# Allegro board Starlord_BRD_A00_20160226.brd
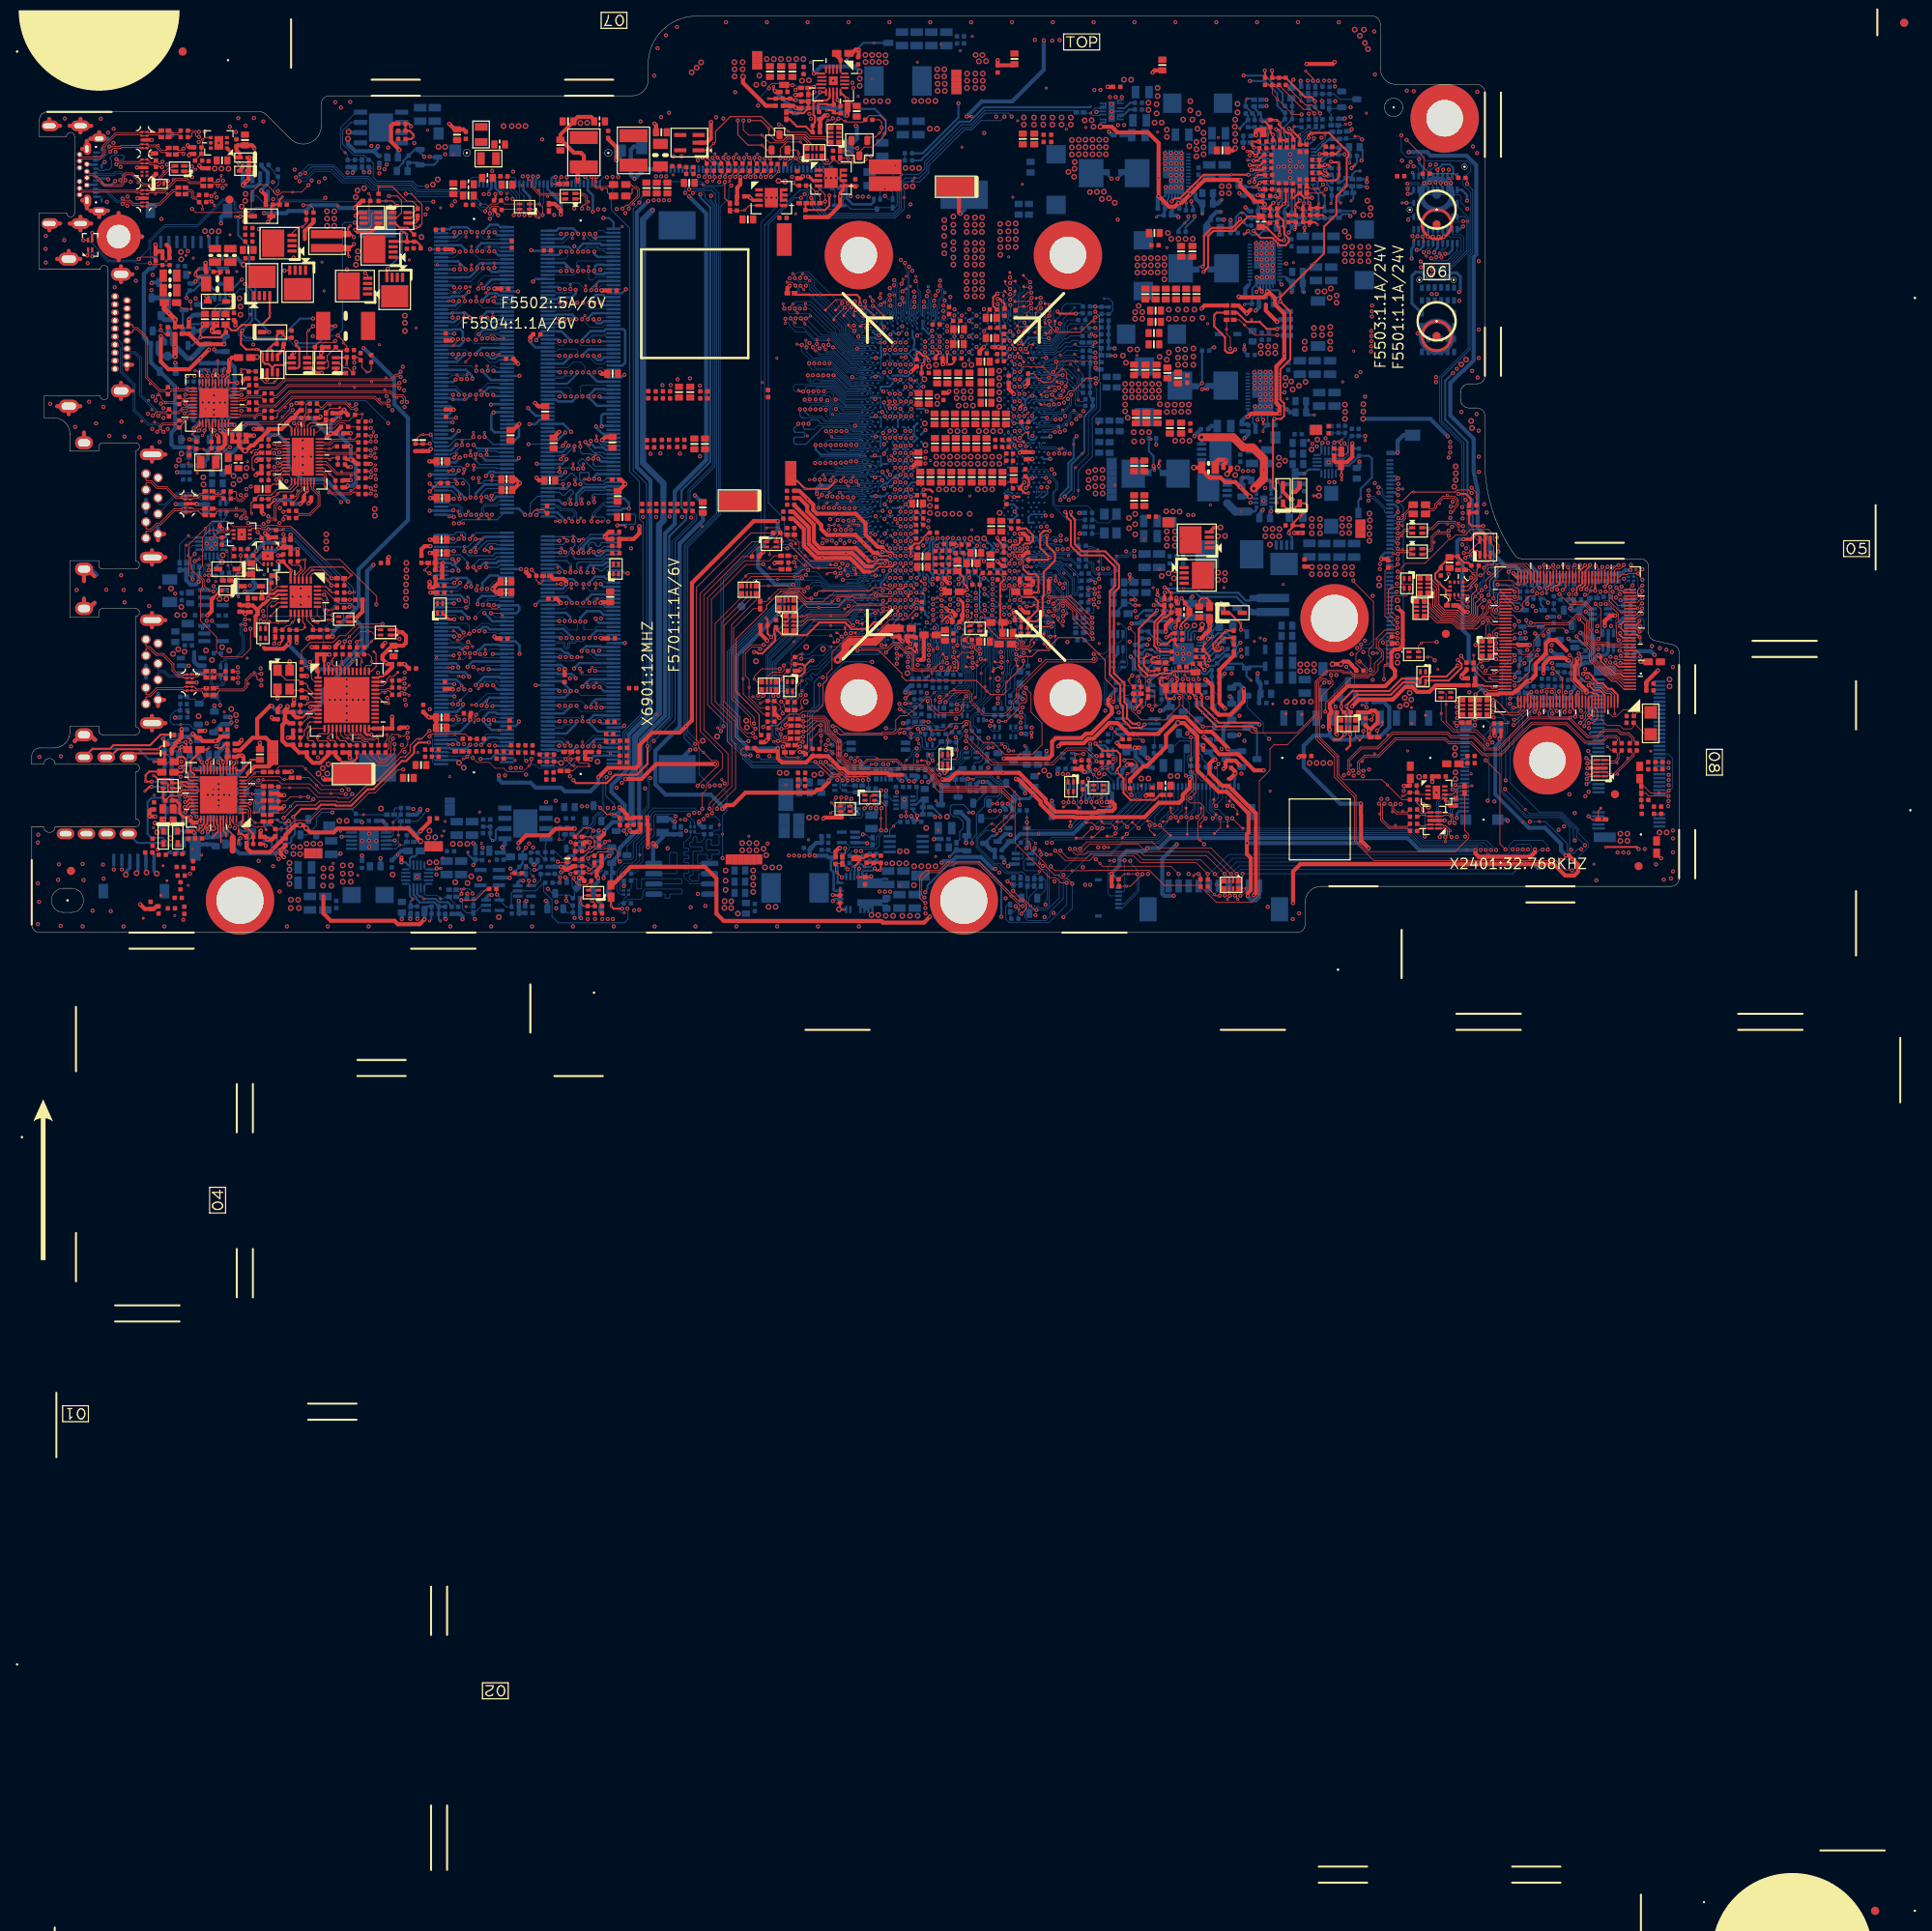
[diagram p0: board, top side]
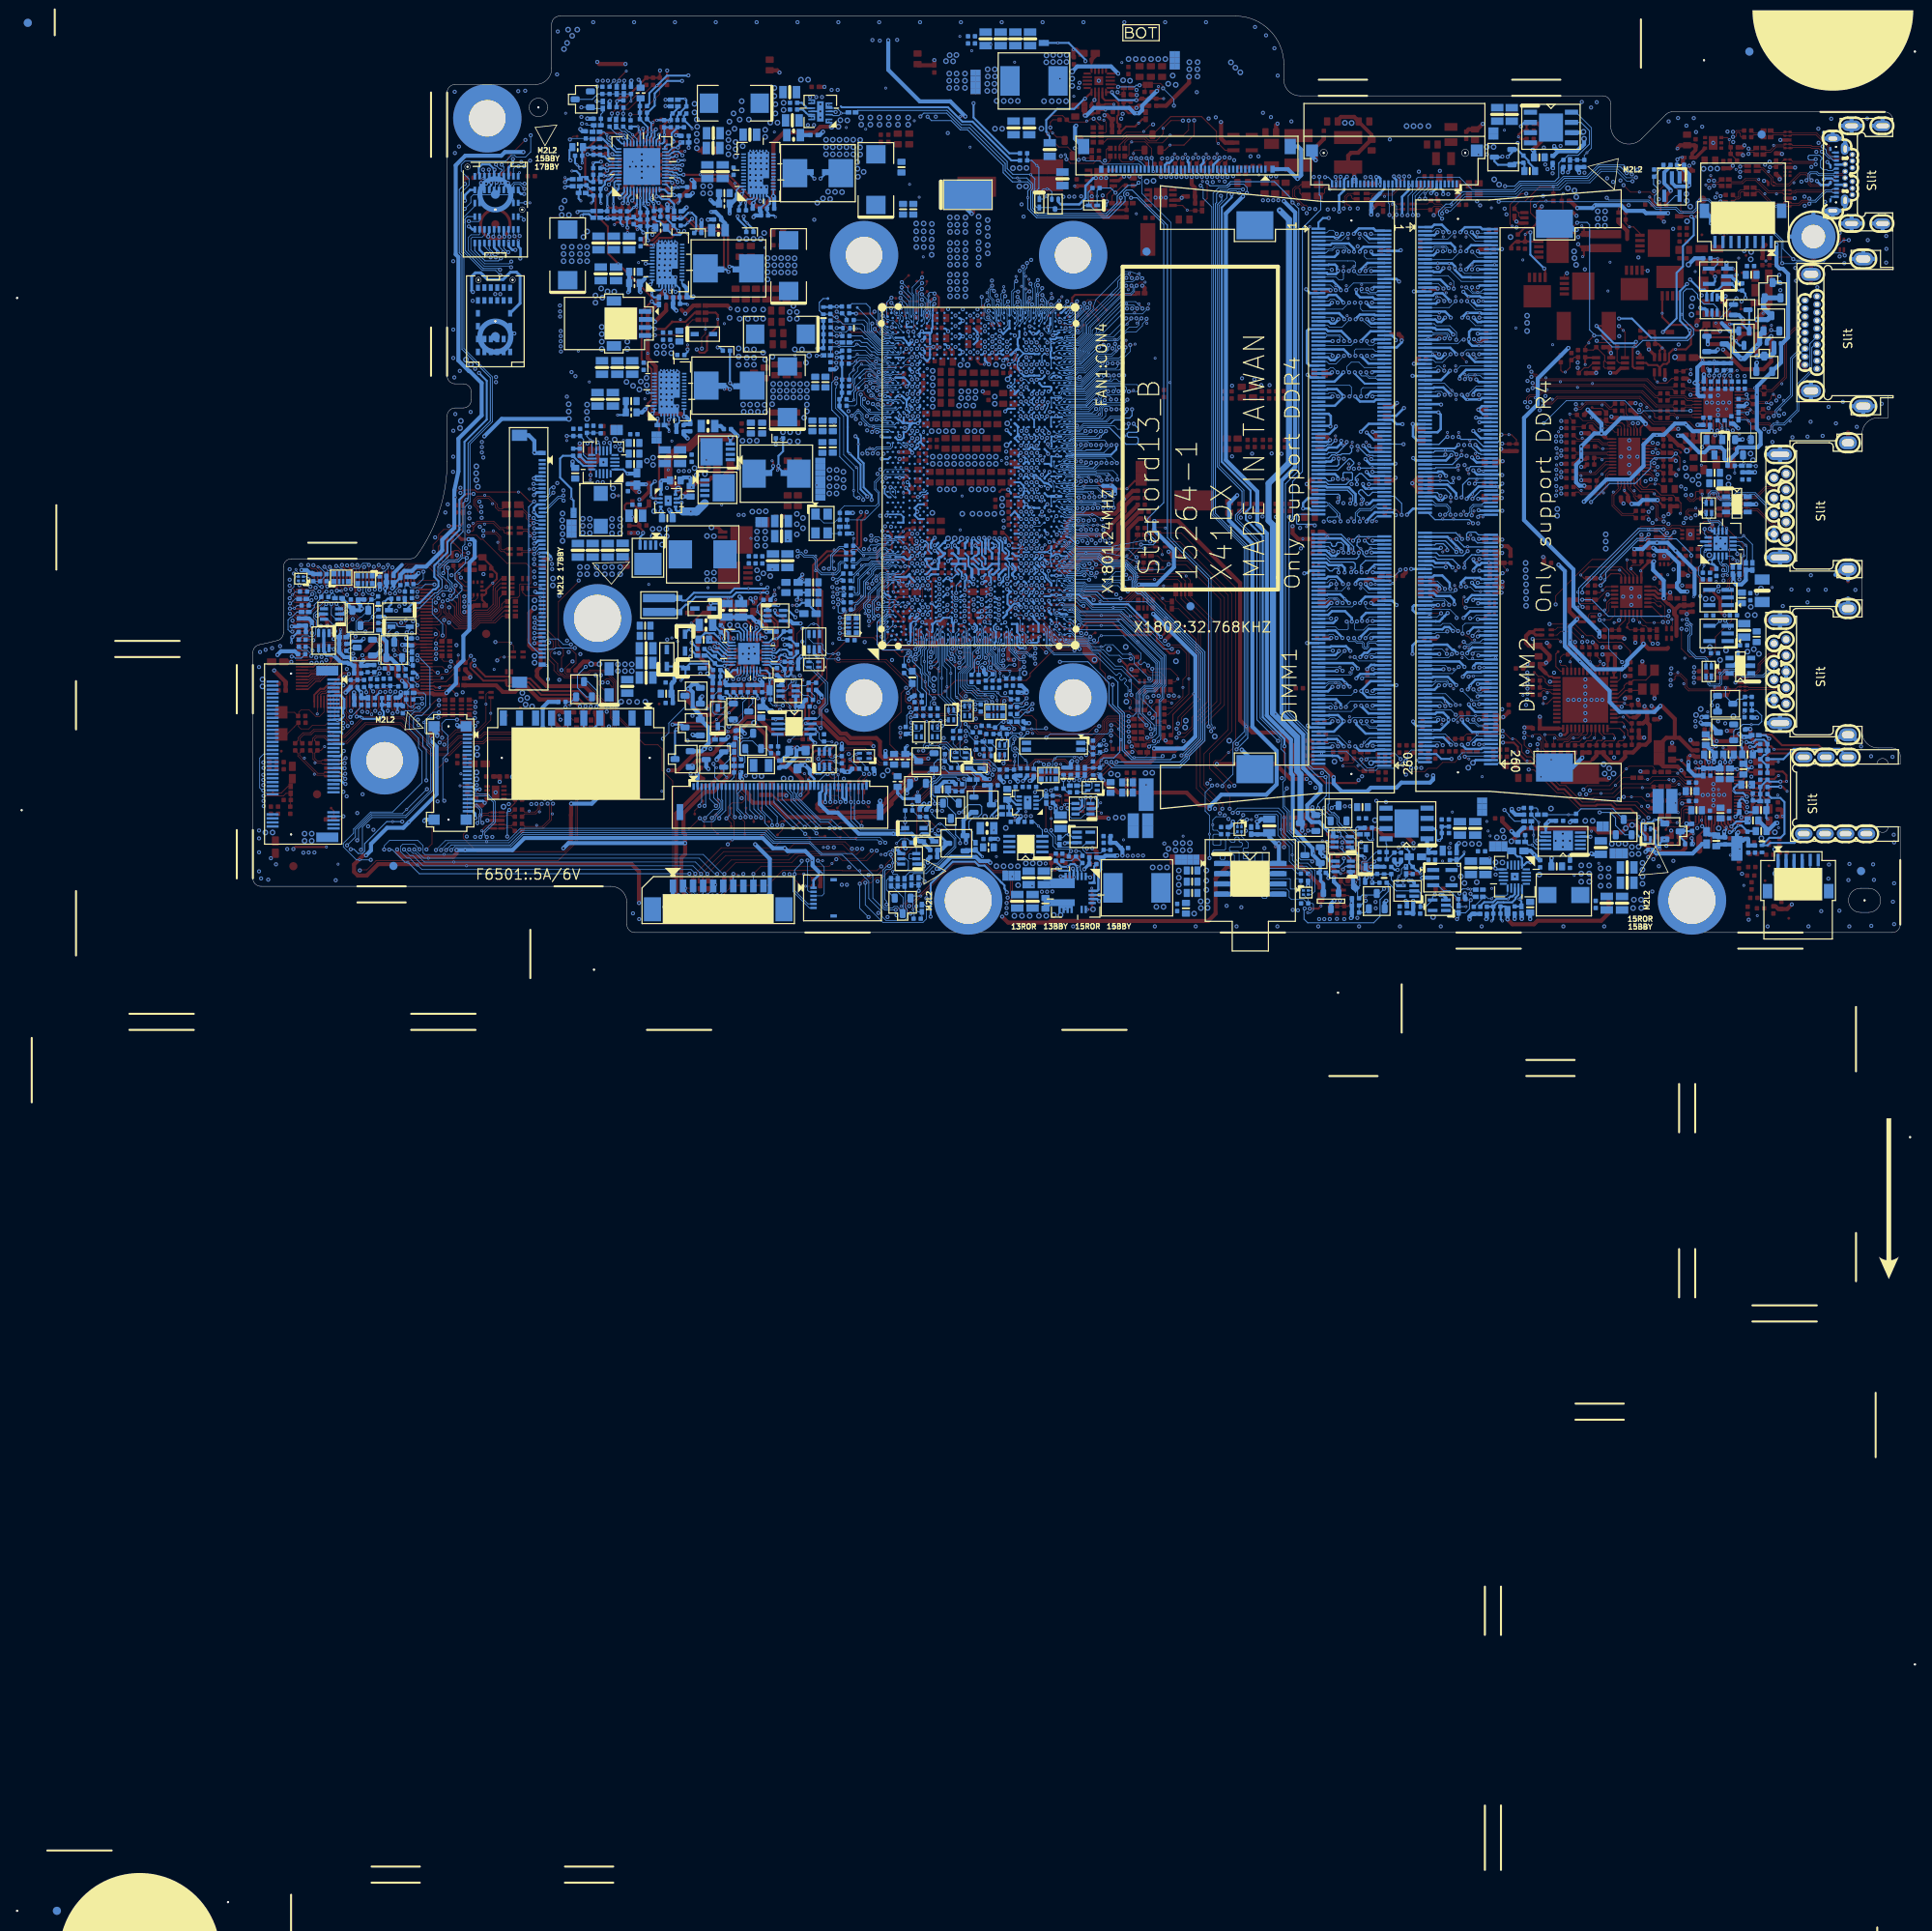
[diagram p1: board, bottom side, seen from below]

Outline 204.85 x 113.92 mm; copper layers: TOP, L2GND, L3, L4, L5VCC, L6, L7GND, BOTTOM. Coordinates in mm from the lower left corner of the outline.

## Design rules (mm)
constraint set DEFAULT: min track width 0.127, pair gap 0.102
net group DDR4_A_BA_40-MW: nets M_A_BA0 M_A_BA1
net group DDR4_A_BG_40-MW: nets M_A_BG0 M_A_BG1
net group DDR4_A_ODT10-MW: nets M_A_DIMA_ODT0 M_A_DIMA_ODT1
net group DDR4_B_BA_40-MW: nets M_B_BA0 M_B_BA1
net group DDR4_B_BG_40-MW: nets M_B_BG0 M_B_BG1
net group DDR4_B_ODT10-MW: nets M_B_DIMB_ODT0 M_B_DIMB_ODT1
net group DDR4_VREF_40: nets V_SM_VREF_CNTA V_SM_VREF_CNTB
net group FAN_TACH: nets FAN1_TACH FAN_TACH1_C
net group I2C_MUX_50: nets MUX_SW0_PD MUX_SW1_PD
net group I2C_TOUCH_PAD-MWS: nets I2C0_SCL_TCH_PAD I2C0_SDA_TCH_PAD
net group POWER_15M: nets Q6205_Q Q6502_D
net group SIGNAL_V_F_8_OHM-MW: nets CFG3 XDP_DBRESET#
net group SIGNAL_V_F_10MIL: nets BEEP FAN_TACH1
net group SIGNAL_V_F_16.5_SVID-MWS: nets VR_SVID_CLK VR_SVID_DATA
net group SIGNAL_V_F_50OHM: nets HDA_CODEC_SYNC HDA_SDIN0
net group XDP_TCLK-MWS: nets XDP_TCK_JTAGX XDP_TCLK
net group AUDIO_12MIL: nets CPVEE
net group AUDIO_BEEP_10MIL: nets AUD_HP1_JACK_L AUD_HP1_JACK_L1 AUD_HP1_JACK_R AUD_HP1_JACK_R1 AUD_PC_BEEP AUD_PC_BEEP_C AUD_PC_BEEP_R AUD_PORTA_L_R_B AUD_PORTA_R_R_B AUD_SENSE AUD_SENSE_A AUD_VREF CBN CBP HDA_SPKR_R JACK_PLUG JACK_PLUG_DET KBC_BEEP_R LINE1-L_C LINE1-L_R LINE1_L LINE1_R LINE1_VREFO_L LINE1_VREFO_R MIC2_VREFO_L MIC2_VREFO_R SPKR
net group AUDIO_BITCLK_50-MWS: nets CODEC_BITCLK_R HDA_BITCLK HDA_CODEC_BITCLK
net group AUDIO_DIGITAL_50-MWS: nets CODEC_SDOUT_R HDA_CODEC_SDIN0 HDA_CODEC_SDOUT HDA_RST# HDA_RST#_R HDA_SDOUT HDA_SYNC
net group CFG_50-MWS: nets CFG0 CFG1 CFG2 CFG4 CFG5 CFG6 CFG7 CFG8 CFG9 CFG10 CFG11 CFG12 CFG13 CFG14 CFG15 CFG16 CFG17 CFG18 CFG19
net group CLK_50-MWS: nets CLK_PCI_LPC CLK_PCI_LPC_MEC SUSCLK SUSCLK_R
net group COMP_20MIL: nets CPU_POPIRCOMP CSI2_COMP EMMC_RCOMP EOPIO_RCOMP PCH_POPIRCOMP SD_RCOMP SM_RCOMP_0 SM_RCOMP_1 SM_RCOMP_2 USBCOMP XCLK_BIASREF
net group CPU_50-MWS: nets CMP_VOUT1 H_PROCHOT#_R PQ4405_3 PWR_CHG_PROCHOT#
net group DDR4_A_CMD_40-MW: nets M_A_A0 M_A_A1 M_A_A2 M_A_A3 M_A_A4 M_A_A5 M_A_A6 M_A_A7 M_A_A8 M_A_A9 M_A_A10 M_A_A11 M_A_A12 M_A_A13 M_A_A14 M_A_A15 M_A_A16 M_A_ACT_N M_A_ALERT_N M_A_PARITY
net group DDR4_A_DATA_00_50-MW: nets M_A_DQ0 M_A_DQ1 M_A_DQ2 M_A_DQ3 M_A_DQ4 M_A_DQ5 M_A_DQ6 M_A_DQ7
net group DDR4_A_DATA_01_50-MW: nets M_A_DQ8 M_A_DQ9 M_A_DQ10 M_A_DQ11 M_A_DQ12 M_A_DQ13 M_A_DQ14 M_A_DQ15
net group DDR4_A_DATA_02_50-MW: nets M_A_DQ16 M_A_DQ17 M_A_DQ18 M_A_DQ19 M_A_DQ20 M_A_DQ21 M_A_DQ22 M_A_DQ23
net group DDR4_A_DATA_03_50-MW: nets M_A_DQ24 M_A_DQ25 M_A_DQ26 M_A_DQ27 M_A_DQ28 M_A_DQ29 M_A_DQ30 M_A_DQ31
net group DDR4_A_DATA_04_50--MW: nets M_A_DQ32 M_A_DQ33 M_A_DQ34 M_A_DQ35 M_A_DQ36 M_A_DQ37 M_A_DQ38 M_A_DQ39
net group DDR4_A_DATA_05_50-MW: nets M_A_DQ40 M_A_DQ41 M_A_DQ42 M_A_DQ43 M_A_DQ44 M_A_DQ45 M_A_DQ46 M_A_DQ47
net group DDR4_A_DATA_06_50-MW: nets M_A_DQ48 M_A_DQ49 M_A_DQ50 M_A_DQ51 M_A_DQ52 M_A_DQ53 M_A_DQ54 M_A_DQ55
net group DDR4_A_DATA_07_50-MW: nets M_A_DQ56 M_A_DQ57 M_A_DQ58 M_A_DQ59 M_A_DQ60 M_A_DQ61 M_A_DQ62 M_A_DQ63
net group DDR4_B_CMD_40--MW: nets M_B_A0 M_B_A1 M_B_A2 M_B_A3 M_B_A4 M_B_A5 M_B_A6 M_B_A7 M_B_A8 M_B_A9 M_B_A10 M_B_A11 M_B_A12 M_B_A13 M_B_A14 M_B_A15 M_B_A16 M_B_ACT_N M_B_ALERT_N M_B_PARITY
net group DDR4_B_DATA_00_50-MW: nets M_B_DQ0 M_B_DQ1 M_B_DQ2 M_B_DQ3 M_B_DQ4 M_B_DQ5 M_B_DQ6 M_B_DQ7
net group DDR4_B_DATA_01_50-MW: nets M_B_DQ8 M_B_DQ9 M_B_DQ10 M_B_DQ11 M_B_DQ12 M_B_DQ13 M_B_DQ14 M_B_DQ15
net group DDR4_B_DATA_02_50-MW: nets M_B_DQ16 M_B_DQ17 M_B_DQ18 M_B_DQ19 M_B_DQ20 M_B_DQ21 M_B_DQ22 M_B_DQ23
net group DDR4_B_DATA_03_50-MW: nets M_B_DQ24 M_B_DQ25 M_B_DQ26 M_B_DQ27 M_B_DQ28 M_B_DQ29 M_B_DQ30 M_B_DQ31
net group DDR4_B_DATA_04_50-MW: nets M_B_DQ32 M_B_DQ33 M_B_DQ34 M_B_DQ35 M_B_DQ36 M_B_DQ37 M_B_DQ38 M_B_DQ39
net group DDR4_B_DATA_05_50-MW: nets M_B_DQ40 M_B_DQ41 M_B_DQ42 M_B_DQ43 M_B_DQ44 M_B_DQ45 M_B_DQ46 M_B_DQ47
net group DDR4_B_DATA_06_50-MW: nets M_B_DQ48 M_B_DQ49 M_B_DQ50 M_B_DQ51 M_B_DQ52 M_B_DQ53 M_B_DQ54 M_B_DQ55
net group DDR4_B_DATA_07_50-MW: nets M_B_DQ56 M_B_DQ57 M_B_DQ58 M_B_DQ59 M_B_DQ60 M_B_DQ61 M_B_DQ62 M_B_DQ63
net group DDR4_CKE_40-MW: nets M_A_CKE0 M_A_CKE1 M_A_CS#0 M_A_CS#1 M_B_CKE0 M_B_CKE1 M_B_CS#0 M_B_CS#1
net group GND: nets MIC_GND
net group JTAG-MW: nets PCH_JTAG_TCK PCH_JTAG_TDI PCH_JTAG_TDO PCH_JTAG_TMS
net group KBC: nets KSI0 KSI1 KSI2 KSI3 KSI4 KSI5 KSI6 KSI7 KSO0 KSO1 KSO2 KSO3 KSO4 KSO5 KSO6 KSO7 KSO8 KSO9 KSO10 KSO11 KSO12 KSO13 KSO14 KSO15 KSO16
net group LCD_BKLT: nets BKLT_CTRL L_BKLT_CTRL LCD_BRIGHTNESS
net group LED: nets BAT1_LED# BAT2_LED# BATT_WHITE_LED# BATT_WHITE_LED_R# CAP_LED# CAP_LED_R# CHG_AMBER_LED# SATA_LED#
net group LED_20MIL: nets AMBER_LED_BAT BAT_AMBER BAT_WHITE CAP_LED CAP_LED_Q CHG_AMBER_LED_R# WHITE_LED_BAT
net group LPC-MWS: nets CLKRUN#_R LPC_FRAME#_DEBUG LPC_LAD0 LPC_LAD0_C LPC_LAD0_R LPC_LAD1 LPC_LAD1_C LPC_LAD1_R LPC_LAD2 LPC_LAD2_C LPC_LAD2_R LPC_LAD3 LPC_LAD3_C LPC_LAD3_R LPC_LFRAME# LPC_LFRAME#_R PCI_CLK_LPC0 PCI_CLK_LPC1 SERIRQ
net group OTHER_4MIL: nets +3VLP A5_TP A67_TP A70_TP AD_IA AUX_EN_WOWL BLON_OUT_C BLUETOOTH_EN BOARD_ID BOARD_ID1 BOARD_ID2 CFG CLKREQ_PCIE#1 CLKREQ_PCIE#2 CLKREQ_PCIE#3 CLKREQ_PCIE#4 CLKREQ_PCIE#5 CLKREQ_PEG#0 COMBO-GPI CPU_DP1_HPD CPU_DP_HPD_MUX CTL1 CTL2 CTL3 DBC_EN_R DBC_PANEL_EN DCIN_EN DDCBUF DGPU_PWR_EN DGPU_PWROK DGPU_PWROK_KBC DVSS EAPD# EC_MUTE# EC_WAKE# EDP_DISP_UTIL EDP_HPD EDP_HPD_CONN EQ FALL_INT2 FAN_PWM1_C FFS_INT2 FFS_INT2_Q FFS_INT2_Q_R GPD11/LANPHYPC GPP_B2/VRALERT# GPP_B4/CPU_GP3 GPP_B18/GSPI0_MOSI GPP_B22 GPP_B23/SML1ALERT# GPP_C2/SMBALERT# GPP_C5/SML0ALERT# GPP_E0/SATAXPCIE0/SATAGP0 GPP_E1/SATAXPCIE1/SATAGP1 GPP_E2/SATAXPCIE2/SATAGP2 GPP_E3/CPU_GP0 GSEN2_INT1_C_HUB GSEN2_INT1_ISH GSEN2_INT2 GSEN2_INT2_C_HUB GSEN2_INT2_ISH GSEN_INT1 GSEN_INT1_HUB GSEN_INT1_ISH GSEN_INT2 GSEN_INT2_HUB GSEN_INT2_ISH GYRO_DRDY_HUB GYRO_DRDY_ISH GYRO_INT GYRO_INT_C GYRO_INT_C_HUB GYRO_INT_ISH GYRO_INT_P11 H_CATERR# HDD_CT HDD_DEVSLP_R HDD_EN HDD_EN_PCH HDMI_EC_DET# HDMI_EC_DET#_C HOST_DEBUG_TX HPD_HDMI_CON HPD_HDMI_CON_C I_ADP I_SYS ICSP_CLR ILIM_HI ILIM_LO ILIM_SEL INT2_SELECT INT#_TYPEC_R INT_TP# IR_CAMERA_DET# IR_CAMERA_DET#_R ISET ISH_KB_DISABLE KB_CLOSE#_2 KB_DISABLE KB_DISABLE_HUB KB_LED_BL_DET_R KB_LED_DET_C KBC_PWRBTN# L_BKLT_EN L_BKLT_EN_EC LCD_TST_C ME_FWP_EC MODEL_ID MSATA_DEVSLP MSATA_DEVSLP_R MSM# MUX_EN MUX_EN_R MUX_HPD_PD MUX_I2C_EN OC_1 OC_2 OVER_CURRENT_P8# P_SYS PBAT_PRES1# PBAT_PRES# PCH_ALW_ON PCH_BATLOW# PCH_THERMTRIP# PCH_WAKE# PD4403_A PD4403_K PIRQA# PME# POWER_SW_IN# PQ4405_2 PQ4405_5 PQ4405_6 PQ4408_C PQ4408_E PRE PROC_SELECT# PS_ID_R PS_ID_R1 PSYS PWR_1D2V_EN PWR_2D5V_EN PWR_CHG_ACOK REXT SA0_CHA_DIM0 SA0_CHB_DIM0 SA1_CHA_DIM0 SA1_CHB_DIM0 SA2_CHA_DIM0 SA2_CHB_DIM0 SIO_EXT_SMI# SIO_EXT_WAKE# SIO_PWRBTN# SIO_SLP_A# SIO_SLP_S5# SIO_SLP_SUS# SKTOCC# SM_INTRUDER# SYS_PRES1# TOUCHPAD_INTR# USB2_ID USB2_VBUSSENSE USB_OC1# USB_OC2# USB_UART_SEL_D9 USBCHARGER_CB0 VBUS_PRODECT# VCREF0 VOL_DOWN# VOL_UP# VR_RDY VRAM_ID1 WIFI_RF_EN ZVM#
net group PECI-MW: nets PECI_EC
net group PLATFORM: nets 1D0V_S5_PWRGD 1D8S_EN_R# 1D8V_EN# 1D8V_EN_R# 1D8V_S5_PWROK 3V5V_S0_ON 3V_5V_POK# 3V_5V_POK_C +SDC_IN_SW +SDC_IN_SW_R1 ALL_SYS_PWRGD_R CPU_DP2_HPD CPU_DP_HPD_R DGPU_HOLD_RST# DS3_PWRCTL EDP_VDD_EN EN_EDRAM_VR GC6_FB_EN_MCP GPU_EVENT# GPU_EVENT_MCP# GSENSOR_CS GSENSOR_SDO H_CPUPWRGD H_VCCST_PWRGD HUB_PA1 HUB_PA2 HUB_PA3 HUB_PA4 HUB_PA5 HUB_PA6 IC_DELAY INT#_TYPEC KB_CLOSE#_2_R LVDS_VDD_EN_R MCU_BOOT0 MCU_OSCI MCU_OSCO MCU_RST# ME_SUS_PWR_ACK ME_SUS_PWR_ACK_R MUX_CDE MUX_CEQ MUX_CEXT MUX_DPEQ MUX_REXT MUX_SSDE MUX_SSEQ MUX_SW2_PD MUX_SW2_PD_R PCH_PLTRST# PCH_RSMRST# PD_CC1 PD_CC1_VCONN_CTRL PD_CC1_VCONN_CTRL_R PD_CC2 PD_CC2_VCONN_CTRL PD_CC2_VCONN_CTRL_R PD_RD1 PD_SWD_CLK PD_SWD_IO PD_VBUS_C_CTRL1 PD_VBUS_C_CTRL1_A PD_VBUS_DISCHG PD_VBUS_P_CTRL1 PD_VBUS_P_CTRL1_R PD_VBUS_R PD_VCCD PD_XRES PLT_RST#_DEBUG PM_RSMRST#_M PM_RSMRST#_R PTP_DIS# PWR_0D6V_S3EN PWR_0D6V_S5EN PWR_0D6V_VCNTL PWR_1D0V_EN PWR_1D0V_PG PWR_1D5V_EN PWR_1D8V_EN PWR_1D8V_POK PWR_2D5V_PG PWR_3D3V_EN PWR_3D3V_EN1 PWR_3V_PG PWR_5V_PG PWR_VCORE_EN RSMRST_PWRGD# RTCRST_ON SATA_ACT# SLP_LAN# SM_DRAMRST# SM_PGCNTL SM_PGCNTL_R SPK_DET# SRTC_RST# SSD_PEDET SUS_STAT#/LPCPD# SUSACK# SUSACK#_R SWCLK SWDIO TP_ON#_GATE TPS70933_EN TS#_DIMM0_1 TS#_DIMM1_1 U4006_CT U4301_IN USB_ADT_SW USB_ADT_SW_R USB_EN# USB_TYPEC_R USBDISABLE VBUS_PRODECT VCCSTG_EN_R VCCSTU_EN_R VCONN1 VCONN2
net group POWER_10M: nets 1.8V_RUN_FB 3D3V_GSEN2 3V5V_CT1 3V5V_CT2 5V_STB +3V_1D8V_AVDD +V1.00U_CPU +VCCAMPHYPLL_1P0 +VCCAPLL_1P0 +VCCCLK2 +VCCCLK4 +VCCCLK5 +VCCCOREG0 +VCCCOREG1 +VCCDSW_1P0 +VCCFUSEPRG +VCCPRTC_3P3 +VCCSFR +VCCST_CPU +VCCSTG BOOST_MON I_BATT LDO1_CAP LDO2_CAP LDO3_CAP MIC_CAP PWR_1D0V_BT PWR_1D0V_FB PWR_1D0V_FB_A PWR_1D0V_PFM PWR_1D0V_SS PWR_1D0V_TON PWR_1D2V_BYP PWR_1D2V_IMAX PWR_1D2V_VFB PWR_1D2V_VFB_R PWR_2D5V_FB PWR_3D3V_FB PWR_3D3V_VOUT PWR_5V_EN PWR_5V_EN1 PWR_5V_EN1_R PWR_5V_FB PWR_5V_FB_A PWR_5V_LDO PWR_5V_VOUT PWR_VCCGT_COMP PWR_VCCGT_COMP_R PWR_VCCGT_CSCOMP PWR_VCCGT_CSNA PWR_VCCGT_CSNB PWR_VCCGT_CSP1 PWR_VCCGT_CSP2 PWR_VCCGT_CSPA PWR_VCCGT_CSPB PWR_VCCGT_CSREF PWR_VCCGT_CSSUM PWR_VCCGT_DIFFOUT PWR_VCCGT_FB PWR_VCCGT_FB_R PWR_VCCGT_ICCMAX PWR_VCCGT_ILIM PWR_VCCGT_ILIM_R PWR_VCCGT_IOUT PWR_VCCGT_NTC PWR_VCCGT_PWMA PWR_VCCGT_PWMB PWR_VCCGT_TSENSE PWR_VCCGT_VCCA PWR_VCCGT_VCCB PWR_VCCGT_VSN PWR_VCCGT_VSN_R PWR_VCCGT_VSP PWR_VCCSA_COMP PWR_VCCSA_COMP_R PWR_VCCSA_CSN PWR_VCCSA_CSN_NTC PWR_VCCSA_CSP PWR_VCCSA_CSP1B PWR_VCCSA_ICCMAX PWR_VCCSA_ILIM PWR_VCCSA_IOUT PWR_VCCSA_VSN PWR_VCCSA_VSN_R PWR_VCCSA_VSP PWR_VCCSA_VSP_R PWR_VCCSA_VSP_RC PWR_VCORE_COMP PWR_VCORE_COMP_R PWR_VCORE_CSN PWR_VCORE_CSNNTC PWR_VCORE_CSP PWR_VCORE_CSP_1A PWR_VCORE_DRVON PWR_VCORE_ICCMAX PWR_VCORE_ILIM PWR_VCORE_IOUT PWR_VCORE_NTC PWR_VCORE_ROSC_COREGT PWR_VCORE_ROSC_SAUS PWR_VCORE_TSENSE PWR_VCORE_VCC_R PWR_VCORE_VR_RDY PWR_VCORE_VRHOT# PWR_VCORE_VRMP PWR_VCORE_VSN PWR_VCORE_VSN_R PWR_VCORE_VSP PWR_VCORE_VSP_R PWR_VCORE_VSP_RC Q6204_G TYPEC_5V TYPEC_5V_SW_R USB_TYPEC_DIS V0.85A_VID0 V0.85A_VID1 VCCRTCEXT
net group POWER_10M_POWER: nets AC_IN#_G ACLIM AD_OFF_L AD_OFF_R PQ3809_D PR_2 PWR_3D3V_FB2 PWR_ASGATE PWR_CHG_1 PWR_CHG_ACDET PWR_CHG_BATDRV PWR_CHG_BATPRES# PWR_CHG_BTST1 PWR_CHG_COMP PWR_CHG_FSET PWR_CHG_IADP PWR_CHG_IDCHG PWR_CHG_ILIM PWR_CHG_NTC PWR_CHG_PMON PWR_CHG_PROG PWR_CHG_REGN PWR_CHG_SRN_1 PWR_CHG_SRP_1 PWR_CMSRC PWR_OPCN PWR_OPCP PWR_VBAT PWR_VCCSA_PWM PWR_VCORE_ADDR_BOOT PWR_VCORE_PWM USB_ADT_D USB_ADT_D1 USB_ADT_R1 USB_TYPEC_SW VCCSA_SENSE VCCSENSE_EDRAM_VR VCCSENSE_EOPIO_VR VDD VSS_AY71 VSSSA_SENSE VSSSENSE_EDRAM_VR VSSSENSE_EOPIO_VR
net group POWER_20M: nets 1D8V_S0 3D3V_AUX_KBC_33 3D3V_AUX_S5 3D3V_SPIVCC1 5V_AUX_S5 +5V_AVDD +RTC_VCC +V_VREF_PATH1 +V_VREF_PATH2 EC_VTT ECVBAT PWR_1D2V_BOOT PWR_1D2V_BOOT_R PWR_3D3V_BOOT PWR_3D3V_BOOT_A PWR_5V_BOOT PWR_5V_BOOT_A PWR_VCCGT_SNUB_1 PWR_VCCGT_SNUB_2 TPAN_VDD VDDIO VREG3PD
net group POWER_20M_POWER: nets 3D3V_MCU BKLGT_PWM CPVDD KB_BL_CTRL# PWR_CHG_VCC PWR_VCCGT_BOOTA PWR_VCCGT_BOOTA_RC PWR_VCCGT_BOOTB PWR_VCCGT_BOOTB_RC PWR_VCCSA_BST PWR_VCCSA_BST_RC PWR_VCCSA_SNUB PWR_VCORE_BOOT PWR_VCORE_BOOT_RC PWR_VCORE_SNUB PWR_VCORE_VCC
net group POWER_25M: nets PQ3802_1 PS_ID_R2 PSID_DISABLE#_R_C
net group POWER_40M: nets DDR_VREF_S3
net group POWER_40M_POWER: nets PWR_VCCSA_DRVH
net group PWR_DISB: nets PWR_VCCGT_DISB#_A PWR_VCCGT_DISB#_B PWR_VCORE_DISB#
net group REF10M: nets VR_CAP
net group SIGNAL_V_F_4MIL: nets 3V_5V_POK AC_DIS AC_PRESENT CLKRUN# FAN1_PWM GPD2/LAN_WAKE# GSEN2_INT1 GSEN2_INT1_C GSEN2_INT2_C GYRO_DRDY HDD_DEVSLP HDD_FALL_INT ITP_PMODE KB_DET# LCD_TST LCD_TST_EN LID_CL_SIO# PLT_RST# RESET_OUT# RTC_DET# USB_CHG_EN USB_OC0# USB_OC3# VCCSTU_EN VR_EN
net group SIGNAL_V_F_5MIL: nets 1D2V_VTT_PWRGD 1D8S_EN# 3V_5V_EN ACOK# ALL_SYS_PWRGD ALWON DDR4_DRAMRST# EXT_PWR_GATE# GC6_FB_EN PANEL_BKEN_EC PCH_DPWROK PM_PCH_PWROK PM_RSMRST# RTC_RST# SIO_SLP_S0# SIO_SLP_S3# SIO_SLP_S4# SYS_PWROK TOUCH_PANEL_INTR# TP_EN#
net group SIGNAL_V_F_10MIL-2: nets ACOK_IN ACOK_IN_M DC_IN_OK HW_ACAVIN_NB#
net group SIGNAL_V_F_14_OHM-MW: nets VR_SVID_ALERT#
net group SIGNAL_V_F_15_OHM-MW: nets H_PECI
net group SIGNAL_V_F_16.5_OHM-MWS: nets PCH_SMBCLK PCH_SMBDATA SPI_CLK_ROM SPI_CS_ROM_N0 SPI_HOLD_ROM SPI_SI_ROM SPI_WP_ROM
net group SIGNAL_V_F_25MIL: nets PS_ID
net group SIGNAL_V_F_50_OHM-MWS: nets CCG2_I2C_SCL CCG2_I2C_SDA H_PROCHOT# MEM_SMBCLK MEM_SMBDATA
net group SMBUS_10MIL: nets PBAT_SMBCLK1 PBAT_SMBDAT1 SMBCLK1 SMBDA1
net group SMBUS_50-MWS: nets CLK_TP_SIO CPU_DP1_CTRL_CLK CPU_DP1_CTRL_DATA CPU_DP2_CTRL_CLK CPU_DP2_CTRL_DATA DAT_TP_SIO DDC_CLK_HDMI DDC_CLK_PH1 DDC_DATA_HDMI DDC_DATA_PH2 DMIC_CLK DMIC_CLK_C DMIC_CLK_R DMIC_DATA DMIC_DATA_C DMIC_DATA_R I2C0_SCL I2C0_SCL_R I2C0_SDA I2C0_SDA_R I2C1_SCL I2C1_SDA I2C_CLK_PD I2C_DATA_PD ICSP_CLOCK ICSP_DATA PWR_CHG_SCL PWR_CHG_SDA SENSOR_I2C_SCL SENSOR_I2C_SCL_2G SENSOR_I2C_SCL_HUB SENSOR_I2C_SDA SENSOR_I2C_SDA_2G SENSOR_I2C_SDA_HUB SMBCLK2 SMBCLK3 SMBDA2 SMBDA3 SML0_SMBCLK SML0_SMBDATA SML1_SMBCLK SML1_SMBDATA THM_SML1_CLK THM_SML1_DATA TPCLK_C TPDATA_C
net group SPI_50-MWS: nets EC_SPI_CLK EC_SPI_MISO EC_SPI_MOSI SIO_EXT_SCI# SIO_RCIN# SPI_CLK_CPU SPI_CLK_ROM_R SPI_CS_CPU_N0 SPI_HOLD_CPU SPI_HOLD_ROM_R SPI_SI_CPU SPI_SI_ROM_R SPI_SO_CPU SPI_SO_ROM SPI_SO_ROM_R SPI_WP_CPU SPI_WP_ROM_R
net group SVID-MW: nets H_CPU_SVIDALRT# H_CPU_SVIDCLK H_CPU_SVIDDAT PWR_VCORE_ALERT# PWR_VCORE_SCLK PWR_VCORE_SDIO
net group T8-MW: nets CMP_VIN0 CMP_VIN0_R CMP_VOUT0 VD_IN1_C
net group TESTPD_4MIL: nets AV1_TP AV71_TP B71_TP BA1_TP BA2_TP BA71_TP BB67_TP BB70_TP C1_TP CPU_A16_TP CPU_D1_TP CPU_D4_TP CPU_D5_TP CPU_D6_TP E71_TP RSVD_F65 RSVD_G65 RSVD_TP_AK12 RSVD_TP_AK13 RSVD_TP_AW70 RSVD_TP_AW71 RSVD_TP_BA68 RSVD_TP_BA70 RSVD_TP_BB68 RSVD_TP_BB69 TP1_AY4 TP2_BB3 TP4_BB5 TP5_AU5 TP6_AT5
net group THERM_SHUTDOWN: nets ALERT# PURE_HW_SHUTDOWN# T_CRIT# THERM_SYS_SHDN#
net group TYPEC_10MIL: nets 3D3V_MUX
net group UART_MW-MW: nets LPSS_UART2_RXD LPSS_UART2_TXD UART0_CTS# UART0_RTS# UART0_TXD UART1_CTS# UART1_RTS#
net group XDP-MW: nets XDP_PRDY# XDP_PREQ# XDP_TDI XDP_TDO_CPU XDP_TMS XDP_TRST#
net group XDP_BPM-MW: nets XDP_BPM0 XDP_BPM1 XDP_BPM2 XDP_BPM3
net group XTAL-MW: nets RTC_X1 RTC_X2 XTAL1 XTAL2 XTAL24_IN XTAL24_OUT XTAL24_OUT_R

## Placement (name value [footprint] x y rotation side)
AFTP2601  AFTE14P-GP  [AFTE14P-75]  152.7 75.91 0 top
AFTP2602  AFTE14P-GP  [AFTE14P-75]  150.8 75.53 0 top
AFTP2603  AFTE14P-GP  [AFTE14P-75]  151.56 77.44 0 top
AFTP2604  AFTE14P-GP  [AFTE14P-75]  153.47 78.07 0 top
AFTP2901  AFTE14P-GP  [AFTE14P-75]  16.81 6.44 90 top
AFTP2902  AFTE14P-GP  [AFTE14P-75]  16.33 8.3 90 top
AFTP2903  AFTE14P-GP  [AFTE14P-75]  16.05 4.61 0 top
AFTP2904  AFTE14P-GP  [AFTE14P-75]  13.87 1.77 0 top
AFTP4301  DO NOT STUFF  [AFTE14P-75]  19.66 82.01 0 top
AFTP4302  DO NOT STUFF  [AFTE14P-75]  19.18 84.17 0 top
AFTP4303  DO NOT STUFF  [AFTE14P-75]  24.66 86.73 0 top
AFTP4304  DO NOT STUFF  [AFTE14P-75]  19.84 77.49 0 top
AFTP4305  DO NOT STUFF  [AFTE14P-75]  21.92 86.58 0 top
AFTP4306  DO NOT STUFF  [AFTE14P-75]  173.3 26.99 0 top
AFTP4307  DO NOT STUFF  [AFTE14P-75]  171.58 27.96 0 top
AFTP4308  DO NOT STUFF  [AFTE14P-75]  171.58 26 0 top
AFTP4309  DO NOT STUFF  [AFTE14P-75]  165.12 23.89 0 top
AFTP4310  DO NOT STUFF  [AFTE14P-75]  163.5 22.8 0 top
AFTP4311  DO NOT STUFF  [AFTE14P-75]  161.92 23.99 0 top
AFTP4312  DO NOT STUFF  [AFTE14P-75]  154.33 28.41 0 top
AFTP4313  DO NOT STUFF  [AFTE14P-75]  157.96 27.12 0 top
AFTP4314  DO NOT STUFF  [AFTE14P-75]  155.95 27.17 0 top
AFTP4315  DO NOT STUFF  [AFTE14P-75]  167.94 26.15 0 top
AFTP4601  DO NOT STUFF  [AFTE14P-75]  164.54 98.98 90 top
AFTP6301  AFTE14P-GP  [AFTE14P-75]  202.36 17.34 0 top
AFTP6303  AFTE14P-GP  [AFTE14P-75]  195.12 15.46 0 top
AFTP6304  AFTE14P-GP  [AFTE14P-75]  201.32 22.55 0 top
AFTP6501  AFTE14P-GP  [AFTE14P-75]  134.95 13.78 0 top
AFTP6502  AFTE14P-GP  [AFTE14P-75]  129.87 11.75 0 top
AFTP6503  AFTE14P-GP  [AFTE14P-75]  131.14 13.66 0 top
AFTP6504  AFTE14P-GP  [AFTE14P-75]  146.99 16.55 0 top
AFTP6505  AFTE14P-GP  [AFTE14P-75]  131.8 11.85 0 top
AFTP6506  AFTE14P-GP  [AFTE14P-75]  133.7 11.98 0 top
AFTP6507  AFTE14P-GP  [AFTE14P-75]  145.41 15.46 0 top
AFTP6508  AFTE14P-GP  [AFTE14P-75]  133.04 13.78 0 top
AFTP6509  AFTE14P-GP  [AFTE14P-75]  135.61 11.78 0 top
AFTP6510  AFTE14P-GP  [AFTE14P-75]  138.76 13.86 0 top
AFTP6511  AFTE14P-GP  [AFTE14P-75]  143.53 15.49 0 top
AFTP6512  AFTE14P-GP  [AFTE14P-75]  136.85 13.68 0 top
AFTP6513  AFTE14P-GP  [AFTE14P-75]  143.69 12.21 0 top
AFTP6514  AFTE14P-GP  [AFTE14P-75]  141.6 12.11 0 top
AFTP6515  AFTE14P-GP  [AFTE14P-75]  139.62 12.13 0 top
AFTP6516  AFTE14P-GP  [AFTE14P-75]  141.63 15.49 0 top
AFTP6517  AFTE14P-GP  [AFTE14P-75]  140.66 13.78 0 top
AFTP6518  AFTE14P-GP  [AFTE14P-75]  142.57 13.78 0 top
AFTP6519  AFTE14P-GP  [AFTE14P-75]  145.36 13.17 0 top
AFTP6520  AFTE14P-GP  [AFTE14P-75]  147.06 12.28 0 top
AFTP6521  AFTE14P-GP  [AFTE14P-75]  148.72 13.2 0 top
AFTP6522  AFTE14P-GP  [AFTE14P-75]  148.92 16.35 0 top
AFTP6523  AFTE14P-GP  [AFTE14P-75]  149.91 14.72 0 top
AFTP6524  AFTE14P-GP  [AFTE14P-75]  150.62 12.95 0 top
AFTP6529  AFTE14P-GP  [AFTE14P-75]  137.97 18.25 0 top
AFTP6530  AFTE14P-GP  [AFTE14P-75]  136.83 20.92 0 top
AFTP6531  AFTE14P-GP  [AFTE14P-75]  125.25 19.75 0 top
AFTP6532  AFTE14P-GP  [AFTE14P-75]  128.29 15.61 0 top
AFTP6533  AFTE14P-GP  [AFTE14P-75]  130.22 15.51 0 top
AFTP6534  AFTE14P-GP  [AFTE14P-75]  132.18 15.49 0 top
AFTP6535  AFTE14P-GP  [AFTE14P-75]  134.11 15.66 0 top
AFTP6536  AFTE14P-GP  [AFTE14P-75]  123.8 12.95 0 top
AFTP6537  AFTE14P-GP  [AFTE14P-75]  129.16 13.81 0 top
AFTP6538  AFTE14P-GP  [AFTE14P-75]  148.84 19.12 0 top
AFTP6539  AFTE14P-GP  [AFTE14P-75]  147.27 14.67 0 top
BATT1  ETY-CON10-28-GP  [50299-01001-002]  164.7 21.71 180 bottom
C701  SC10U6D3V3MX-GP  [C603H38]  115.21 68.93 0 top
C702  SC10U6D3V3MX-GP  [C603H38]  116.61 68.93 0 top
C703  SC10U6D3V3MX-GP  [C603H38]  113.87 68.93 0 top
C704  SC10U6D3V3MX-GP  [C603H38]  112.6 68.93 0 top
C715  SC10U6D3V3MX-GP  [C603H38]  110.26 59.02 0 top
C716  SC1U10V2KX-1GP  [C402H22]  123.92 46.78 180 top
C717  SC1U10V2KX-1GP  [C402H22]  123.92 39.34 180 top
C718  SCD1U16V2KX-3GP  [C402H22]  77.4 60.76 0 top
C719  SC1U10V2KX-1GP  [C402H22]  76.51 60.76 0 top
C720  SCD1U16V2KX-3GP  [C402H22]  120.88 48.48 180 top
C721  SCD1U16V2KX-3GP  [C402H22]  120.88 46.8 0 top
C1101  SC1U10V2KX-1GP  [C402H22]  121.49 60.8 180 top
C1102  DO NOT STUFF  [C402H22]  126.77 98.72 180 top
C1103  DO NOT STUFF  [C402H22]  112.47 75.58 90 top
C1104  DO NOT STUFF  [C402H22]  118.31 72 270 top
C1105  SC1U10V2KX-1GP  [C402H22]  125.83 98.72 180 top
C1106  DO NOT STUFF  [C402H22]  139.67 85.44 90 top
C1107  SC1U10V2KX-1GP  [C402H22]  119.63 75.18 90 top
C1108  DO NOT STUFF  [C402H22]  110.41 51.48 270 top
C1109  SC1U10V2KX-1GP  [C402H22]  112.52 53.36 180 top
C1110  SC1U10V2KX-1GP  [C402H22]  110.54 54.37 270 top
C1111  SC1U10V2KX-1GP  [C402H22]  110.44 52.29 270 top
C1112  SC22U6D3V3MX-1-GP  [C603H40]  118.49 36.16 270 top
C1113  SC22U6D3V3MX-1-GP  [C603H40]  110.77 45.46 270 top
C1114  SC1U10V2KX-1GP  [C402H22]  120.11 44.31 180 top
C1115  SC22U6D3V3MX-1-GP  [C603H40]  119.23 46.35 180 top
C1116  SC1U10V2KX-1GP  [C402H22]  113.64 46.6 90 top
C1117  SC1U10V2KX-1GP  [C402H22]  113.69 47.46 90 top
C1118  SC22U6D3V3MX-1-GP  [C603H40]  117.4 47.18 90 top
C1119  SC1U10V2KX-1GP  [C402H22]  115.37 47.18 270 top
C1120  SC10U6D3V3MX-GP  [C603H38]  116.94 45.91 270 top
C1121  SC1U10V2KX-1GP  [C402H22]  116.08 48.23 270 top
C1122  SC22U6D3V3MX-1-GP  [C603H40]  113.56 36.95 0 top
C1123  SC10U6D3V3MX-GP  [C603H38]  110.77 46.75 270 top
C1124  SC1U10V2KX-1GP  [C402H22]  120.67 60.8 180 top
C1125  SC1U10V2KX-1GP  [C402H22]  119.81 60.8 180 top
C1126  SC1U10V2KX-1GP  [C402H22]  121.18 59.1 180 top
C1127  SC1U10V2KX-1GP  [C402H22]  122.02 59.1 180 top
C1202  SC10U6D3V3MX-GP  [C603H38]  63.85 64.76 180 top
C1203  SC10U6D3V3MX-GP  [C603H38]  64.9 60.85 180 top
C1204  SC10U6D3V3MX-GP  [C603H38]  64.43 56.2 270 top
C1205  SC10U6D3V3MX-GP  [C603H38]  72.86 54.24 180 top
C1206  SC10U6D3V3MX-GP  [C603H38]  72.21 60.93 180 top
C1207  SC1U10V2KX-1GP  [C402H22]  73.56 21.15 90 top
C1208  SC10U6D3V3MX-GP  [C603H38]  73.46 51.65 90 top
C1209  SC10U6D3V3MX-GP  [C603H38]  71.93 41.72 0 top
C1210  SC10U6D3V3MX-GP  [C603H38]  72.24 69.46 270 top
C1211  SC4D7U6D3V2MX-1-GP  [C402H22]  71.42 24.22 180 top
C1212  SC4D7U6D3V2MX-1-GP  [C402H22]  72.31 24.22 180 top
C1213  SC1U10V2KX-L1-GP  [C402H22]  73.56 21.99 90 top
C1214  SC1U10V2KX-1GP  [C402H22]  72.29 79.8 270 top
C1215  SC1U10V2KX-1GP  [C402H22]  62.81 74.36 270 top
C1216  SC1U10V2KX-1GP  [C402H22]  64.11 84.78 90 top
C1217  SC1U10V2KX-1GP  [C402H22]  64.69 41.49 90 top
C1218  SC1U10V2KX-1GP  [C402H22]  66.27 31.59 180 top
C1219  SC1U10V2KX-1GP  [C402H22]  72.63 56.31 90 top
C1220  SC1U10V2KX-1GP  [C402H22]  72.08 36.57 270 top
C1221  SC1U10V2KX-1GP  [C402H22]  72.03 26.18 270 top
C1222  SCD022U16V2KX-3GP  [C402H22]  72.61 48.92 270 top
C1223  SC4D7U6D3V2MX-1-GP  [C402H22]  64.95 21.68 180 top
C1224  SC4D7U6D3V2MX-1-GP  [C402H22]  63.17 21.68 180 top
C1225  SC1U10V2KX-1GP  [C402H22]  64.44 19.9 90 top
C1226  SC1U10V2KX-1GP  [C402H22]  64.44 19.02 90 top
C1227  SC4D7U6D3V2MX-1-GP  [C402H22]  64.06 21.68 180 top
C1228  SCD1U16V2KX-L-GP  [C402H22]  70.08 22.44 90 top
C1229  SCD1U16V2KX-3GP  [C402H22]  72.63 47.18 90 top
C1230  SC4D7U6D3V2MX-1-GP  [C402H22]  50.6 22.32 180 top
C1231  SC4D7U6D3V2MX-1-GP  [C402H22]  62.28 22.83 180 top
C1232  SC4D7U6D3V2MX-1-GP  [C402H22]  73.58 22.95 90 top
C1301  SCD1U16V2KX-3GP  [C402H22]  50.85 42.26 270 top
C1303  SC10U6D3V3MX-GP  [C603H38]  59.54 61.81 180 top
C1304  SC10U6D3V3MX-GP  [C603H38]  58.98 42.31 270 top
C1305  SC10U6D3V3MX-GP  [C603H38]  58.98 43.65 270 top
C1306  SC10U6D3V3MX-GP  [C603H38]  59.08 55.01 90 top
C1307  SC10U6D3V3MX-GP  [C603H38]  59.05 56.35 90 top
C1308  SC10U6D3V3MX-GP  [C603H38]  50.95 47.18 270 top
C1309  SC10U6D3V3MX-GP  [C603H38]  51.03 54.02 270 top
C1310  SC10U6D3V3MX-GP  [C603H38]  51 58.56 270 top
C1311  SC4D7U6D3V2MX-1-GP  [C402H22]  61.39 22.83 180 top
C1312  SC4D7U6D3V2MX-1-GP  [C402H22]  60.5 22.83 180 top
C1313  SC1U10V2KX-1GP  [C402H22]  58.7 22.06 180 top
C1314  SC1U10V2KX-L1-GP  [C402H22]  57.81 22.06 180 top
C1315  SC1U10V2KX-1GP  [C402H22]  51.51 64.56 180 top
C1316  SC1U10V2KX-1GP  [C402H22]  51.38 30.73 0 top
C1317  SC1U10V2KX-1GP  [C402H22]  54.18 27.27 90 top
C1318  SC1U10V2KX-1GP  [C402H22]  58.72 36.54 270 top
C1319  SC1U10V2KX-1GP  [C402H22]  51.48 74.03 0 top
C1320  SC1U10V2KX-1GP  [C402H22]  59.43 71.31 90 top
C1321  SC1U10V2KX-1GP  [C402H22]  58.8 80.03 270 top
C1322  SC1U10V2KX-1GP  [C402H22]  50.98 84.93 90 top
C1323  SCD022U16V2KX-3GP  [C402H22]  50.6 44.16 90 top
C1324  SC10U6D3V3MX-GP  [C603H38]  48.41 20.82 270 top
C1325  SC10U6D3V3MX-GP  [C603H38]  46.84 19.22 270 top
C1326  SC1U10V2KX-1GP  [C402H22]  49.76 22.29 180 top
C1327  SC1U10V2KX-1GP  [C402H22]  48.92 22.29 180 top
C1328  SCD1U16V2KX-L-GP  [C402H22]  56.54 22.52 90 top
C1329  SC2D2U10V3KX-L-GP  [C603H36]  50.93 25.44 270 top
C1330  SC4D7U6D3V2MX-1-GP  [C402H22]  59.61 22.83 180 top
C1331  SC4D7U6D3V2MX-1-GP  [C402H22]  73.58 23.84 90 top
C1601  SCD1U16V2KX-3GP  [C402H22]  130.66 46.37 90 bottom
C1602  SCD1U16V2KX-3GP  [C402H22]  130.66 45.48 90 bottom
C1605  SCD22U10V2KX-1GP  [C402H22]  130.94 42.82 90 bottom
C1606  SCD22U10V2KX-1GP  [C402H22]  130.94 41.93 90 bottom
C1607  SCD22U10V2KX-1GP  [C402H22]  130.94 40.15 90 bottom
C1608  SCD22U10V2KX-1GP  [C402H22]  130.94 41.04 90 bottom
C1609  SCD22U10V2KX-1GP  [C402H22]  130.99 43.73 90 bottom
C1610  SCD22U10V2KX-1GP  [C402H22]  130.99 44.62 90 bottom
C1611  SCD22U10V2KX-1GP  [C402H22]  130.63 47.19 90 bottom
C1612  SCD22U10V2KX-1GP  [C402H22]  130.63 48.08 90 bottom
C1701  SC220P50V2KX-3GP  [C402H22]  113.56 22.8 270 bottom
C1702  SCD1U16V2KX-3GP  [C402H22]  61.8 3.24 90 bottom
C1703  SCD1U16V2KX-3GP  [C402H22]  61.82 2.43 90 bottom
C1704  SC10U6D3V3MX-GP  [C603H38]  98.19 18.03 0 bottom
C1710  SCD47U10V2KX-GP  [C402H22]  67.56 8.7 0 top
C1711  SCD01U50V2KX-1GP  [C402H22]  65.05 7.74 0 bottom
C1801  SC15P50V2JN-2-GP  [C402H22]  131.42 52.16 270 bottom
C1802  SC15P50V2JN-2-GP  [C402H22]  131.42 49.6 270 bottom
C1803  SC3P50V2CN-1-GP  [C402H22]  100.38 21.71 0 bottom
C1804  SC3P50V2CN-1-GP  [C402H22]  100.38 23.41 180 bottom
C1805  SC1U10V2KX-1GP  [C402H22]  70.03 2.84 0 top
C1806  SC1U10V2KX-1GP  [C402H22]  67.74 4.26 270 bottom
C2101  SC1U10V2KX-1GP  [C402H22]  120.93 45.13 0 top
C2102  SC1U10V2KX-1GP  [C402H22]  95.73 19.85 90 top
C2103  SC1U10V2KX-1GP  [C402H22]  109.93 36.21 180 top
C2104  SC1U10V2KX-1GP  [C402H22]  109.98 49.42 180 top
C2105  SC1U10V2KX-1GP  [C402H22]  112.39 45.3 180 top
C2106  SC1U10V2KX-1GP  [C402H22]  112.39 46.98 0 top
C2107  SC1U10V2KX-1GP  [C402H22]  113.09 44.01 90 top
C2108  SC1U10V2KX-1GP  [C402H22]  114.6 36.75 0 top
C2109  SC1U10V2KX-1GP  [C402H22]  116.89 44.87 270 top
C2110  SCD1U16V2KX-3GP  [C402H22]  114.07 45.3 180 top
C2111  SCD1U16V2KX-3GP  [C402H22]  113.23 45.3 180 top
C2112  SCD1U16V2KX-3GP  [C402H22]  91.06 38.19 270 top
C2113  SC22U6D3V3MX-1-GP  [C603H40]  121.36 37.25 90 top
C2114  SC22U6D3V3MX-1-GP  [C603H40]  115.11 45.58 180 top
C2115  SC22U6D3V3MX-1-GP  [C603H40]  135.18 42.26 90 bottom
C2116  SC1U10V2KX-1GP  [C402H22]  110.41 50.66 270 top
C2117  SC1U10V2KX-1GP  [C402H22]  109.75 47.82 90 top
C2118  SCD1U16V2KX-3GP  [C402H22]  112.11 49.7 90 top
C2119  SC22U6D3V3MX-1-GP  [C603H40]  135.18 43.53 90 bottom
C2120  SC1U10V2KX-1GP  [C402H22]  95.73 19.04 90 top
C2121  SC1U10V2KX-1GP  [C402H22]  113.89 48.3 270 top
C2122  SC22U6D3V3MX-1-GP  [C603H40]  135.18 40.99 90 bottom
C2402  AZ5725-01FDR7G-GP  [SOD882-10D6-1H20]  189.08 43.78 180 bottom
C2403  AZ5725-01FDR7G-GP  [SOD882-10D6-1H20]  189.25 39.69 180 bottom
C2405  SC100P50V2JN-3GP  [C402H22]  178.87 32.71 270 top
C2406  SCD1U16V2KX-3GP  [C402H22]  179.02 31.59 270 top
C2407  SCD1U16V2KX-3GP  [C402H22]  188.59 31.11 180 bottom
C2408  SCD1U16V2KX-3GP  [C402H22]  189.76 32.81 180 bottom
C2409  SCD01U50V2KX-1GP  [C402H22]  197.33 44.11 0 bottom
C2410  SCD1U16V2KX-3GP  [C402H22]  198.27 38.6 180 bottom
C2411  SCD1U16V2KX-3GP  [C402H22]  185.52 41.57 270 bottom
C2412  SCD1U16V2KX-3GP  [C402H22]  192.23 41.39 90 bottom
C2413  SCD1U16V2KX-3GP  [C402H22]  191.79 29.15 90 bottom
C2414  SCD1U16V2KX-3GP  [C402H22]  185.08 36.11 0 bottom
C2416  SCD1U16V2KX-3GP  [C402H22]  201.22 30.09 270 top
C2418  SC1U10V2KX-1GP  [C402H22]  198.7 37.35 90 bottom
C2420  SCD1U16V2KX-3GP  [C402H22]  187.07 28.74 0 bottom
C2421  SCD1U16V2KX-3GP  [C402H22]  201.22 30.95 270 top
C2422  SCD1U16V2KX-3GP  [C402H22]  191.82 33.16 90 bottom
C2423  SCD1U16V2KX-3GP  [C402H22]  187.81 44.34 90 bottom
C2424  SC10P50V2JN-4GP  [C402H22]  198.78 26.92 90 top
C2425  SC10P50V2JN-4GP  [C402H22]  198.75 26.08 90 top
C2426  SC1U10V2KX-1GP  [C402H22]  191.84 30.95 180 bottom
C2427  SC2200P50V2KX-2GP  [C402H22]  186.31 31.92 270 bottom
C2428  SCD1U16V2KX-3GP  [C402H22]  193.67 35.88 90 bottom
C2429  SCD1U16V2KX-3GP  [C402H22]  199.13 38.6 180 bottom
C2435  SC2200P50V2KX-2GP  [C402H22]  189.41 31.03 0 bottom
C2441  SC2200P50V2KX-2GP  [C402H22]  189.25 28.31 270 bottom
C2501  SC10U10V5KX-2GP  [C805H54]  78.46 13.25 0 bottom
C2502  SCD1U16V2KX-3GP  [C402H22]  79.91 12.65 0 bottom
C2503  SCD47U10V2KX-GP  [C402H22]  70.92 2.84 0 top
C2601  SC10U6D3V3MX-GP  [C603H38]  141.63 27.37 0 bottom
C2602  SCD1U16V2KX-3GP  [C402H22]  136.07 28.08 270 bottom
C2603  SC2200P50V2KX-2GP  [C402H22]  152.96 74.13 180 bottom
C2604  SC4D7U6D3V3KX-GP  [C603H36]  151.81 74.13 180 bottom
C2605  SCD1U16V2KX-3GP  [C402H22]  153.85 74.13 180 bottom
C2606  SC470P50V3JN-2GP  [C603H36]  46.07 94.66 90 bottom
C2607  SC2200P50V2KX-2GP  [C402H22]  46.86 96.13 0 bottom
C2608  SCD1U16V2KX-3GP  [C402H22]  136.47 23.59 0 top
C2609  SCD1U16V2KX-3GP  [C402H22]  135.66 23.59 0 top
C2610  SCD1U16V2KX-3GP  [C402H22]  144.83 24.63 0 bottom
C2612  SCD1U16V2KX-3GP  [C402H22]  123.87 32.71 180 bottom
C2613  SC100P50V2JN-3GP  [C402H22]  195.91 41.72 90 bottom
C2701  SCD1U16V2KX-3GP  [C402H22]  23.62 19.96 180 bottom
C2702  SC10U6D3V3MX-GP  [C603H38]  17.3 12.62 270 bottom
C2703  SC1U10V3KX-3GP  [C603H36]  21.35 22.11 90 bottom
C2704  SC1U10V3KX-3GP  [C603H36]  21.18 19.73 0 bottom
C2705  SC2D2U10V3KX-1GP  [C603H36]  18.31 13.94 270 bottom
C2706  SC10U6D3V3MX-GP  [C603H38]  22.35 14.85 0 bottom
C2707  SCD1U16V2KX-3GP  [C402H22]  21.28 14.65 0 bottom
C2708  SC10U6D3V3MX-GP  [C603H38]  25.32 15.21 90 bottom
C2709  SCD1U16V2KX-3GP  [C402H22]  23.67 14.7 0 bottom
C2710  SCD1U16V2KX-3GP  [C402H22]  21.77 11.4 180 bottom
C2711  SC4D7U6D3V3KX-GP  [C603H36]  22.88 11.4 180 bottom
C2712  SC10U6D3V3MX-GP  [C603H38]  23.72 22.11 270 bottom
C2713  SC10U6D3V3MX-GP  [C603H38]  19.1 18.38 90 bottom
C2714  SC1U10V2KX-1GP  [C402H22]  18.9 27.6 90 bottom
C2715  SC4D7U6D3V3KX-GP  [C603H36]  24.18 23.97 180 bottom
C2716  SC4D7U6D3V3KX-GP  [C603H36]  26.01 17.57 90 bottom
C2717  SCD1U16V2KX-3GP  [C402H22]  25.83 16.35 90 bottom
C2718  SC10U6D3V3MX-GP  [C603H38]  28.37 22.14 180 top
C2719  SCD1U16V2KX-3GP  [C402H22]  25.83 18.63 90 bottom
C2720  SCD1U16V2KX-3GP  [C402H22]  26.31 10.99 90 bottom
C2721  SCD1U16V2KX-3GP  [C402H22]  24.05 26.36 0 bottom
C2722  SCD1U16V2KX-3GP  [C402H22]  18.92 26.76 90 bottom
C2723  SC33P50V2JN-3GP  [C402H22]  30.68 15.89 180 top
C2724  SC4D7U6D3V3KX-GP  [C603H36]  22.45 19.73 180 bottom
C2902  SC10U6D3V3MX-GP  [C603H38]  19.51 20.31 180 bottom
C2907  SC10U6D3V3MX-GP  [C603H38]  17.32 15.21 90 bottom
C2908  SC10U6D3V3MX-GP  [C603H38]  18.99 22.14 90 bottom
C3401  SC1U10V2KX-1GP  [C402H22]  18.82 56.76 0 bottom
C3402  SCD1U16V2KX-3GP  [C402H22]  22.86 44.77 180 bottom
C3403  SCD1U16V2KX-3GP  [C402H22]  19.63 56.76 0 bottom
C3404  SC22U6D3V3MX-1-GP  [C603H40]  23.09 57.14 270 bottom
C3405  SC22U6D3V3MX-1-GP  [C603H40]  23.09 55.85 270 bottom
C3502  SCD1U16V2KX-3GP  [C402H22]  23.7 39.41 90 bottom
C3503  SCD1U16V2KX-3GP  [C402H22]  23.1 34.71 90 bottom
C3507  SCD1U16V2KX-3GP  [C402H22]  18.64 41.75 0 bottom
C3508  SC1U10V2KX-1GP  [C402H22]  19.48 35.7 90 bottom
C3512  SC22U6D3V5MX-2GP  [C805H58]  19.4 37.56 180 bottom
C3513  SC10U6D3V3MX-GP  [C603H38]  19.68 41.6 0 bottom
C3514  SC10U6D3V3MX-GP  [C603H38]  17.85 36.77 180 bottom
C3601  SCD1U16V2KX-3GP  [C402H22]  24.31 53.94 270 top
C3602  SCD1U16V2KX-3GP  [C402H22]  24.31 54.83 270 top
C3603  SCD1U16V2KX-3GP  [C402H22]  24.56 31.59 270 top
C3604  SCD1U16V2KX-3GP  [C402H22]  24.56 32.48 270 top
C3701  SCD1U16V2KX-3GP  [C402H22]  27.66 39.84 270 top
C3702  SCD1U16V2KX-3GP  [C402H22]  25.83 40.33 0 top
C3703  SC1U10V2KX-1GP  [C402H22]  31.29 46.57 180 top
C3704  SC1U10V2KX-1GP  [C402H22]  29.82 43.93 180 top
C3705  SCD1U16V2KX-3GP  [C402H22]  34.97 37.18 180 top
C3706  SCD1U16V2KX-3GP  [C402H22]  32.94 37.18 0 top
C3707  SC1U50V3KX-GP  [C603H32]  23.67 95.98 90 top
C3708  SCD1U25V2KX-GP  [C402H22]  20.65 97.6 270 top
C3709  SCD1U16V2KX-3GP  [C402H22]  25.45 98.16 180 top
C3710  SC2D2U10V3KX-1GP  [C603H36]  26.52 98.52 180 top
C3711  SC390P50V2KX-GP  [C402H22]  32.18 48.35 180 top
C3712  SC390P50V2KX-GP  [C402H22]  25.17 47.24 180 top
C3713  SC10U6D3V3MX-GP  [C603H38]  27.28 45.24 0 top
C3714  SCD1U16V2KX-3GP  [C402H22]  26.44 47.67 270 top
C3801  SCD1U16V2KX-3GP  [C402H22]  35.02 64.86 270 top
C3802  SCD1U16V2KX-3GP  [C402H22]  35.02 65.75 270 top
C3803  SCD1U16V2KX-3GP  [C402H22]  32.43 51.53 90 top
C3804  SCD1U16V2KX-3GP  [C402H22]  32.43 52.42 90 top
C3805  SCD1U16V2KX-3GP  [C402H22]  31.93 53.31 90 top
C3806  SCD1U16V2KX-3GP  [C402H22]  31.93 54.19 90 top
C3807  SCD1U16V2KX-3GP  [C402H22]  41.07 57.37 270 top
C3808  SCD1U16V2KX-3GP  [C402H22]  41.07 60.04 270 top
C3809  SCD1U16V2KX-3GP  [C402H22]  41.07 59.15 270 top
C3810  SCD1U16V2KX-3GP  [C402H22]  41.07 61.81 270 top
C3811  SCD1U16V2KX-3GP  [C402H22]  41.07 60.93 270 top
C3812  SCD1U16V2KX-3GP  [C402H22]  41.07 54.5 270 top
C3813  SCD1U16V2KX-3GP  [C402H22]  41.07 55.39 270 top
C3814  SCD1U16V2KX-3GP  [C402H22]  41.07 56.48 270 top
C3815  SCD1U16V2KX-3GP  [C402H22]  41.07 58.26 90 top
C3816  SCD1U16V2KX-3GP  [C402H22]  29.01 62.58 270 top
C3817  SCD1U16V2KX-3GP  [C402H22]  38.3 62.04 90 top
C3818  SCD1U16V2KX-3GP  [C402H22]  34.3 54.07 90 top
C3819  SCD1U16V2KX-3GP  [C402H22]  33.58 65.37 180 top
C3820  SC2D2U10V3KX-1GP  [C603H36]  28.7 55.13 270 top
C3821  SCD1U25V2KX-GP  [C402H22]  21.99 95.44 0 top
C3861  SCD1U16V2KX-3GP  [C402H22]  18.97 99.69 270 top
C3862  SCD1U16V2KX-3GP  [C402H22]  18.97 98.87 270 top
C3863  SCD1U16V2KX-3GP  [C402H22]  21.26 91.69 270 top
C3864  SCD1U16V2KX-3GP  [C402H22]  21.26 90.8 270 top
C4001  SC470P50V2KX-3GP  [C402H22]  137.62 102.3 270 bottom
C4002  SC470P50V2KX-3GP  [C402H22]  137.62 103.14 270 bottom
C4004  SC10U10V5KX-2GP  [C805H54]  138.1 104.46 270 bottom
C4005  SC10U10V5KX-2GP  [C805H54]  137.77 100.96 270 bottom
C4006  SC10U6D3V3MX-GP  [C603H38]  89.05 88.64 270 top
C4007  SCD1U16V2KX-3GP  [C402H22]  93.42 88.84 270 top
C4008  SCD1U16V2KX-3GP  [C402H22]  96.21 89.37 0 top
C4009  SC10U6D3V3MX-GP  [C603H38]  119.07 17.8 270 bottom
C4010  SC10U10V5KX-2GP  [C805H54]  104.19 93.69 0 bottom
C4011  SCD1U16V2KX-3GP  [C402H22]  102.41 93.18 0 top
C4012  SC10U6D3V3MX-GP  [C603H38]  111.05 17.19 0 bottom
C4013  SC10U10V5KX-2GP  [C805H54]  104.42 13.76 0 bottom
C4014  SCD1U16V2KX-3GP  [C402H22]  98.63 11.98 90 bottom
C4015  SC1U10V2KX-1GP  [C402H22]  95.2 94.2 0 top
C4017  SCD1U16V2KX-3GP  [C402H22]  109.57 18.1 90 bottom
C4023  SC1U10V2KX-1GP  [C402H22]  74.85 13.83 0 top
C4028  SCD1U16V2KX-3GP  [C402H22]  76.12 13.45 90 top
C4029  SCD1U16V2KX-3GP  [C402H22]  76.12 14.29 90 top
C4031  SC1U10V2KX-1GP  [C402H22]  107.9 18.1 270 bottom
C4032  SC1U10V2KX-1GP  [C402H22]  88.16 91.51 270 top
C4033  SC1U10V2KX-1GP  [C402H22]  87.68 90.19 180 top
C4034  SC1U10V2KX-1GP  [C402H22]  105.38 16.58 180 bottom
C4101  SC1U10V2KX-1GP  [C402H22]  113.56 11.62 90 bottom
C4102  SC1U10V2KX-1GP  [C402H22]  110.16 13.76 90 bottom
C5501  SCD1U16V2KX-3GP  [C402H22]  89.28 95.14 180 top
C5502  SC4D7U6D3V3KX-GP  [C603H36]  78.28 99.48 270 top
C5503  SC4D7U6D3V3KX-GP  [C603H36]  59.1 92.96 90 top
C5504  SCD1U16V2KX-3GP  [C402H22]  90.17 95.14 180 top
C5505  SC4D7U6D3V3KX-GP  [C603H36]  81.76 93.18 270 top
C5506  SCD1U16V2KX-3GP  [C402H22]  91.06 95.14 180 top
C5507  SCD1U16V2KX-3GP  [C402H22]  81.84 94.3 270 top
C5508  SC1U10V2KX-1GP  [C402H22]  81.84 95.14 90 top
C5509  SCD1U16V2KX-3GP  [C402H22]  91.95 95.14 180 top
C5510  SCD1U16V2KX-3GP  [C402H22]  83.95 95.14 180 top
C5511  SCD1U16V2KX-3GP  [C402H22]  84.83 95.14 180 top
C5512  SCD1U50V3KX-GP  [C603H36]  79.04 92.55 0 top
C5513  SC1KP50V2KX-1GP  [C402H22]  80.08 95.27 90 top
C5514  SC2D2U35V3KX-GP  [C603H40]  77.72 92.55 0 top
C5515  SC4D7U6D3V3KX-GP  [C603H36]  52.88 99.18 180 top
C5516  SCD1U50V3KX-GP  [C603H36]  65.73 97.88 0 top
C5517  SC4D7U6D3V3KX-GP  [C603H36]  66.69 100.83 270 top
C5518  SC2D2U35V3KX-GP  [C603H40]  76.43 92.55 0 top
C5519  SCD1U16V2KX-3GP  [C402H22]  88.39 95.14 180 top
C5531  SCD1U16V2KX-3GP  [C402H22]  86.61 95.14 180 top
C5532  SCD1U16V2KX-3GP  [C402H22]  85.72 95.14 180 top
C5533  SCD1U16V2KX-3GP  [C402H22]  87.5 95.14 180 top
C5534  SC1KP50V2KX-1GP  [C402H22]  54.43 90.47 270 top
C5542  SCD1U50V3KX-GP  [C603H36]  54.3 91.61 90 top
C5701  SCD1U16V2KX-3GP  [C402H22]  24.05 66.67 270 bottom
C5702  SCD1U16V2KX-3GP  [C402H22]  24.43 68.04 0 bottom
C5703  SCD1U16V2KX-3GP  [C402H22]  23.67 63.55 180 bottom
C5704  SCD1U16V2KX-3GP  [C402H22]  24.48 63.54 180 bottom
C5705  SCD1U16V2KX-3GP  [C402H22]  19.33 68.04 0 bottom
C5706  SCD1U16V2KX-3GP  [C402H22]  20.14 68.04 0 bottom
C5707  SCD1U16V2KX-3GP  [C402H22]  29.39 67.02 270 top
C5708  SCD1U16V2KX-3GP  [C402H22]  29.39 63.97 270 top
C5709  SCD1U16V2KX-3GP  [C402H22]  27.48 67.15 270 top
C5710  SCD1U16V2KX-3GP  [C402H22]  29.39 66.13 270 top
C5711  SCD1U16V2KX-3GP  [C402H22]  29.39 64.86 270 top
C5712  SCD1U16V2KX-3GP  [C402H22]  27.48 65.88 270 top
C5713  SCD1U16V2KX-3GP  [C402H22]  19.58 59.81 180 top
C5714  SCD1U16V2KX-3GP  [C402H22]  27.48 68.04 270 top
C5715  SCD1U16V2KX-3GP  [C402H22]  27.48 64.99 270 top
C5716  SCD1U16V2KX-3GP  [C402H22]  21 63.72 180 bottom
C6001  SCD01U50V2KX-1GP  [C402H22]  171.83 12.62 90 top
C6002  SCD1U16V2KX-3GP  [C402H22]  178.53 21.51 180 top
C6003  SCD01U50V2KX-1GP  [C402H22]  171.83 13.51 90 top
C6004  SC2D2U10V2KX-GP  [C402H22]  179.42 21.51 180 top
C6005  SCD01U50V2KX-1GP  [C402H22]  171.83 15.29 90 top
C6006  SCD01U50V2KX-1GP  [C402H22]  171.83 14.4 90 top
C6007  SCD1U16V2KX-3GP  [C402H22]  177.09 16.22 0 top
C6008  SCD1U16V2KX-3GP  [C402H22]  171.78 18.28 270 top
C6009  SC1U6D3V2KX-GP  [C402H22]  173.71 19.4 90 top
C6010  SCD1U16V2KX-3GP  [C402H22]  175.39 19.4 270 top
C6301  SCD22U10V2KX-1GP  [C402H22]  196.82 23.08 180 top
C6302  SCD22U10V2KX-1GP  [C402H22]  199.59 23.08 180 top
C6303  SCD22U10V2KX-1GP  [C402H22]  198.7 23.08 180 top
C6304  SC33P50V2JN-3GP  [C402H22]  201.9 20.74 0 top
C6305  SC33P50V2JN-3GP  [C402H22]  201.01 20.74 0 top
C6306  SCD047U25V2KX-GP  [C402H22]  202.61 15.21 180 top
C6307  SCD1U16V2KX-3GP  [C402H22]  202.79 20.74 0 top
C6308  SCD047U25V2KX-GP  [C402H22]  201.73 15.21 180 top
C6309  SCD22U10V2KX-1GP  [C402H22]  197.71 23.08 180 top
C6501  SCD1U16V2KX-3GP  [C402H22]  139.37 17.57 0 top
C6502  SCD1U16V2KX-3GP  [C402H22]  118.79 21.73 180 bottom
C6503  SCD1U16V2KX-3GP  [C402H22]  126.19 21.45 0 bottom
C6504  SCD1U16V2KX-3GP  [C402H22]  130.99 20.59 270 top
C6901  SC1U10V2KX-1GP  [C402H22]  45.26 25.37 90 top
C6902  SCD1U16V2KX-3GP  [C402H22]  32.94 28.29 270 top
C6903  SCD01U50V2KX-1GP  [C402H22]  31.04 26.51 270 top
C6904  SCD01U50V2KX-1GP  [C402H22]  45.26 33.37 90 top
C6905  SCD01U50V2KX-1GP  [C402H22]  31.04 27.4 270 top
C6906  SCD1U16V2KX-3GP  [C402H22]  36.37 35.02 180 top
C6907  SCD1U16V2KX-3GP  [C402H22]  35.48 35.02 180 top
C6908  SC15P50V2JN-2-GP  [C402H22]  33.58 29.66 0 top
C6909  SC15P50V2JN-2-GP  [C402H22]  33.55 31.46 180 top
C7001  SCD047U16V2KX-1-GP  [C402H22]  17.14 83.4 180 top
C7002  SCD1U16V2KX-3GP  [C402H22]  16.66 84.67 90 top
C7003  SCD1U16V2KX-3GP  [C402H22]  175.21 44.82 0 top
C7004  SC10U6D3V3MX-GP  [C603H38]  176.3 45.99 0 top
CPU1  SKYLAKE-U-GP  [BGA1356M4224-U2H52]  114.6 56.71 270 bottom
D401  RB751V-40H-GP  [SOD323AKH38]  122.6 12.97 270 bottom
D502  AZ5725-01FDR7G-GP  [SOD882-10D6-1H20]  100.35 20.03 0 bottom
D1701  RB751V-40H-GP  [SOD323AKH38]  66.47 9.31 180 bottom
D2402  RB751V-40H-GP  [SOD323AKH38]  186.49 38.02 270 bottom
D2403  RB751V-40H-GP  [SOD323AKH38]  186.79 40.07 90 bottom
D2501  BAS40C-2-GP  [SOT-23-9H44]  70.79 3.9 0 bottom
D2601  RB551V30-1-GP  [SOD323AKH44]  148.77 74.39 270 bottom
D2701  BAT54C-7-F-3-GP  [SOT23-2D4-312H48]  28.32 12.56 270 bottom
D3701  RB521CM-30T2R-GP-U  [SOD923-10D6AKH16]  26.41 94.68 90 top
D3702  RB521CM-30T2R-GP-U  [SOD923-10D6AKH16]  26.41 96.33 90 top
D3703  RB551V30-GP  [SOD323AKH38]  24.33 45.18 90 top
D3704  RB551V30-GP  [SOD323AKH38]  27.38 43.04 270 top
D4001  LBAS16LT1G-GP  [SOT23-2D4-312H44]  118.06 15.13 0 bottom
D4002  BAS16-6-GP  [SOT23-2D4-312H44]  163.83 103.57 90 bottom
D4003  RB521CM-30T2R-GP-U  [SOD923-10D6AKH16]  100.38 90.39 90 bottom
D4004  RB521CM-30T2R-GP-U  [SOD923-10D6AKH16]  107.06 90.64 0 bottom
D4304  LBAV99LT1G-1-GP  [SOT23-2D4-312H44]  150.16 29.43 90 bottom
D4305  LBAV99LT1G-1-GP  [SOT23-2D4-312H44]  150.16 25.49 90 bottom
D4306  LBAV99LT1G-1-GP  [SOT23-2D4-312H44]  151.41 21.56 90 bottom
D5501  BAT54C-7-F-3-GP  [SOT23-2D4-312H48]  92.99 98.21 0 top
D5502  BAT54C-7-F-3-GP  [SOT23-2D4-312H48]  102.92 97.5 180 top
D5701  BAW56-9-GP  [SOT-23-10H44]  23.11 60.32 0 bottom
D7001  BAT54A-7-F-2-GP  [SOT23-2D4-312H48]  124.05 3.32 0 bottom
DB1  PAD-10P-177042-GP  [PAD-10P-177042]  146.99 2.89 180 bottom
DB3  ACES-CON6-58-GP  [50696-00601-001]  132.64 4.31 90 bottom
DCIN1  ACES-CON8-13-GP-U1  [50224-0080N-W02]  19.55 89.71 0 bottom
DM1  DDR4-260P-24-GP  [ADDR0107-P005A]  68.25 54.11 90 bottom
DM2  DDR4-260P-23-GP  [ADDR0106-P005A]  55 54.31 270 bottom
EC401  AZ5725-01FDR7G-GP  [SOD882-10D6-1H20]  131.04 75.12 270 bottom
EC1001  DO NOT STUFF  [C402H22]  121.21 53.69 180 top
EC1002  DO NOT STUFF  [C402H22]  143.69 68.8 180 top
EC1003  DO NOT STUFF  [C402H22]  144.07 62.83 0 top
EC1004  DO NOT STUFF  [C402H22]  123.49 63.47 270 top
EC1005  SC1U10V2KX-1GP  [C402H22]  114.07 77.31 0 top
EC1006  DO NOT STUFF  [C402H22]  115.03 76.04 270 top
EC1007  DO NOT STUFF  [C402H22]  121.79 50.69 0 top
EC1102  SC2D2U10V2KX-GP  [C402H22]  91.57 67 180 top
EC1103  SC2D2U10V2KX-GP  [C402H22]  59.69 85.56 180 top
EC1202  SC2D2U10V2KX-GP  [C402H22]  74.73 30.37 90 top
EC1302  SC2D2U10V2KX-GP  [C402H22]  50.7 87.37 90 top
EC1303  SC2D2U10V2KX-GP  [C402H22]  59.41 25.9 0 top
EC1701  AZ5725-01FDR7G-GP  [SOD882-10D6-1H20]  133.91 77.31 0 bottom
EC1702  AZ5725-01FDR7G-GP  [SOD882-10D6-1H20]  123.44 37.96 270 top
EC1703  AZ5725-01FDR7G-GP  [SOD882-10D6-1H20]  113.49 21.96 270 bottom
EC1704  AZ5725-01FDR7G-GP  [SOD882-10D6-1H20]  103.15 20.06 0 bottom
EC1705  AZ5725-01FDR7G-GP  [SOD882-10D6-1H20]  66.6 8.27 0 top
EC1706  SC1KP50V2KX-1GP  [C402H22]  118.72 44.72 90 top
EC1707  SCD1U16V2KX-3GP  [C402H22]  107.75 19.9 180 bottom
EC1708  AZ5725-01FDR7G-GP  [SOD882-10D6-1H20]  64.18 7.71 0 bottom
EC1709  AZ5725-01FDR7G-GP  [SOD882-10D6-1H20]  60.12 3.22 270 bottom
EC1710  SC2D2U10V2KX-GP  [C402H22]  96.47 10.51 270 bottom
EC1711  AZ5725-01FDR7G-GP  [SOD882-10D6-1H20]  104.04 20.06 0 bottom
EC1712  SCD1U16V2KX-3GP  [C402H22]  68.12 11.01 90 top
EC1713  SC2D2U10V2KX-GP  [C402H22]  60.5 7.38 90 top
EC1801  SC10P50V2JN-4GP  [C402H22]  92.35 28.34 0 top
EC1802  SC10P50V2JN-4GP  [C402H22]  92.35 26.66 180 top
EC1803  SC4D7P50V2BN-GP  [C402H22]  94.38 50.28 90 top
EC1806  SCD1U16V2KX-3GP  [C402H22]  69.14 2.84 0 top
EC1807  SCD1U16V2KX-3GP  [C402H22]  69.14 6.42 270 top
EC1808  SCD1U16V2KX-3GP  [C402H22]  67.74 3.37 270 bottom
EC1901  SC10P50V2JN-4GP  [C402H22]  90.02 46.73 270 top
EC1902  SCD1U16V2KX-3GP  [C402H22]  93.65 45.99 270 top
EC2002  SC1KP50V2KX-1GP  [C402H22]  116.46 36.39 90 top
EC2101  SCD1U25V2KX-GP  [C402H22]  95.73 18.2 90 top
EC2501  SC4D7P50V2BN-GP  [C402H22]  74.06 3.62 270 bottom
EC2502  SC4D7P50V2BN-GP  [C402H22]  83.62 12.67 0 bottom
EC2503  SC10P50V2JN-4GP  [C402H22]  74.09 6.44 90 bottom
EC2701  SC33P50V2JN-3GP  [C402H22]  29.28 15.51 90 top
EC2703  SCD1U25V2KX-GP  [C402H22]  15.04 11.22 0 top
EC2704  SC1KP50V2KX-1GP  [C402H22]  19.48 12.13 0 top
EC2705  SCD1U25V2KX-GP  [C402H22]  14.55 9.95 90 top
EC2706  SC1KP50V2KX-1GP  [C402H22]  18.06 10.38 180 bottom
EC2707  SC1KP50V2KX-1GP  [C402H22]  18.9 10.38 180 bottom
EC2708  SC33P50V2JN-3GP  [C402H22]  31.01 19.96 90 top
EC2709  SC33P50V2JN-3GP  [C402H22]  30.68 17.67 0 top
EC2901  SC100P50V2JN-3GP  [C402H22]  18.97 2.76 0 top
EC2902  SC100P50V2JN-3GP  [C402H22]  18.49 5.81 180 top
EC2903  SC100P50V2JN-3GP  [C402H22]  20.06 8.42 0 top
EC2904  SC100P50V2JN-3GP  [C402H22]  20.75 11.7 270 top
EC2905  SC100P50V2JN-3GP  [C402H22]  15.21 15.74 0 top
EC2906  SC100P50V2JN-3GP  [C402H22]  17.07 16.43 90 top
EC2907  SC100P50V2JN-3GP  [C402H22]  18.34 16.86 0 bottom
EC2908  SC100P50V2JN-3GP  [C402H22]  16.97 20.69 270 bottom
EC2909  SC100P50V2JN-3GP  [C402H22]  18.59 7.08 90 top
EC2910  SC100P50V2JN-3GP  [C402H22]  15.77 2.81 180 top
EC2911  SC100P50V2JN-3GP  [C402H22]  16.23 9.67 270 top
EC2912  SC100P50V2JN-3GP  [C402H22]  14.78 3.37 0 top
EC4001  SCD1U16V2KX-3GP  [C402H22]  98.22 10.71 0 bottom
EC4301  SC10U25V3MX-GP  [C603H40]  18.54 81.75 90 bottom
EC4302  SCD1U25V2KX-GP  [C402H22]  18.62 82.85 90 bottom
EC4306  DO NOT STUFF  [C402H22]  165.86 26.18 180 top
EC4307  DO NOT STUFF  [C402H22]  153.08 28.54 90 bottom
EC4308  DO NOT STUFF  [C603H36]  153.47 29.68 90 bottom
EC4309  DO NOT STUFF  [C402H22]  162.74 27.37 270 top
EC4310  DO NOT STUFF  [C402H22]  164.46 27.37 90 top
EC4425  SC2D2U10V2KX-GP  [C402H22]  158.27 45.94 0 top
EC4534  SC2D2U10V2KX-GP  [C402H22]  161.26 62.5 0 top
EC5501  SC6D8P50V2DN-GP  [C402H22]  99.64 96.74 180 top
EC5502  SCD1U25V2KX-GP  [C402H22]  58.72 94 90 top
EC5503  SC22P50V2JN-4GP  [C402H22]  57.91 91 270 top
EC5504  SC22P50V2JN-4GP  [C402H22]  57.99 89.83 270 top
EC5505  SC33P50V2JN-3GP  [C402H22]  53.97 99.1 180 top
EC6401  SC220P50V2KX-3GP  [C402H22]  120.19 9.36 270 bottom
EC6402  SC220P50V2KX-3GP  [C402H22]  112.67 18.3 90 bottom
EC6501  SC33P50V2JN-3GP  [C402H22]  128.12 20.36 90 bottom
EC6502  SC33P50V2JN-3GP  [C402H22]  129.89 20.36 270 bottom
EC6503  SC33P50V2JN-3GP  [C402H22]  131.62 20.59 180 bottom
EC6504  SC33P50V2JN-3GP  [C402H22]  131.62 22.37 0 bottom
EC6601  SC33P50V2JN-3GP  [C402H22]  169.14 36.34 0 top
EC6602  SC33P50V2JN-3GP  [C402H22]  168.68 45.81 180 top
EC6603  SC33P50V2JN-3GP  [C402H22]  165.15 32.55 270 top
EC8901  SCD1U25V2KX-GP  [C402H22]  23.49 24.81 180 top
EC8902  SC1KP50V2KX-1GP  [C402H22]  19.3 24.78 0 bottom
EC8903  SCD1U25V2KX-GP  [C402H22]  24.33 24.81 180 top
EC8904  SC1KP50V2KX-1GP  [C402H22]  20.88 24.63 180 top
EC8905  SC1U50V3KX-GP  [C603H32]  52.42 92.47 0 top
EC8906  SC2200P50V2KX-2GP  [C402H22]  139.37 51.71 270 top
EC8907  SCD1U25V2KX-GP  [C402H22]  49.93 14.19 270 top
EC8908  SCD1U25V2KX-GP  [C402H22]  158.67 21.94 270 top
EC8909  SCD1U25V2KX-GP  [C402H22]  48.69 27.86 0 top
EC8910  SCD1U25V2KX-GP  [C402H22]  47.34 32.83 270 top
EC8911  SCD1U25V2KX-GP  [C402H22]  43.86 45.94 90 top
EC8912  SCD1U25V2KX-GP  [C402H22]  60.15 2.35 270 bottom
EC8913  SCD1U25V2KX-GP  [C402H22]  25.14 76.57 0 top
EC8914  SCD1U25V2KX-GP  [C402H22]  31.55 11.27 0 top
EC8915  SCD1U25V2KX-GP  [C402H22]  120.11 107.36 180 top
EC8916  SCD1U25V2KX-GP  [C402H22]  134.92 105.12 270 top
EC8917  SCD1U25V2KX-GP  [C402H22]  71.68 99.2 0 top
EC8918  SC1KP50V2KX-1GP  [C402H22]  76.66 66.85 180 top
EC8919  SCD1U25V2KX-GP  [C402H22]  77.6 66.83 180 top
EC8920  SCD1U25V2KX-GP  [C402H22]  78.36 60.8 0 top
EC8921  SCD1U25V2KX-GP  [C402H22]  79.25 60.8 0 top
EC8922  SCD1U25V2KX-GP  [C402H22]  80.27 60.8 0 top
EC8923  SCD1U25V2KX-GP  [C402H22]  78.49 66.83 180 top
EC8924  SCD1U25V2KX-GP  [C402H22]  79.38 66.83 180 top
EC8925  SCD1U25V2KX-GP  [C402H22]  83.14 66.83 180 top
EC8926  SC2D2U10V2KX-GP  [C402H22]  170.23 94.02 90 top
EC8927  SC1U50V3KX-GP  [C603H32]  122.2 108.6 0 top
EC8928  SC1U50V3KX-GP  [C603H32]  140.59 107.84 0 top
EC8929  SC1U50V3KX-GP  [C603H32]  148.05 97.22 90 top
EC8933  SC2200P50V2KX-2GP  [C402H22]  75.92 52.84 0 top
EC8934  SC2200P50V2KX-2GP  [C402H22]  76.81 52.84 0 top
EC8935  SC2200P50V2KX-2GP  [C402H22]  77.67 52.84 0 top
EC8936  SCD1U25V2KX-GP  [C402H22]  78.56 52.84 0 top
EC8937  SCD1U25V2KX-GP  [C402H22]  79.43 52.83 0 top
EC8938  SCD1U25V2KX-GP  [C402H22]  80.31 52.83 0 top
ED1217  AZ5725-01FDR7G-GP  [SOD882-10D6-1H20]  48.61 60.29 0 top
ED1302  AZ5725-01FDR7G-GP  [SOD882-10D6-1H20]  47.72 60.29 0 top
ED2901  AZ2025-01H-R7G-GP  [SOD-523-4H28]  16.36 11.83 0 top
ED2902  AZ5725-01FDR7G-GP  [SOD882-10D6-1H20]  17.19 10.41 180 bottom
ED2903  AZ5725-01FDR7G-GP  [SOD882-10D6-1H20]  16.97 22.29 90 top
ED2904  AZ5725-01FDR7G-GP  [SOD882-10D6-1H20]  17.37 23.44 90 top
ED2905  AZ5725-01FDR7G-GP  [SOD882-10D6-1H20]  18.18 24.55 90 top
ED2906  AZ2025-01H-R7G-GP  [SOD-523-4H28]  18.16 11.83 0 top
ED3801  AZ5315-02F-GP  [SOT883-1D0-321H20]  24.05 42.51 90 top
ED6301  L05ESDL5V0NA-4-GP  [SLP2510P8-1H22]  195.12 20.44 90 top
ED6401  PESD5V0S1BB-GP-U  [SOD-523-2H26]  120.88 11.32 90 bottom
ED6402  PESD5V0S1BB-GP-U  [SOD-523-2H26]  115.01 20.41 90 bottom
EL2901  BLM15PD121SN1D-GP  [L402H22]  18.46 8.14 90 top
EL2902  BLM15PD121SN1D-GP  [L402H22]  18.26 9.77 90 top
EL2903  BLM15PD121SN1D-GP  [L402H22]  18.21 4.31 90 top
EL2904  BLM15PD121SN1D-GP  [L402H22]  17.37 3.01 90 top
EL4301  0R5J-5-GP  [R805H24]  22.78 84.17 0 top
EL4302  0R5J-5-GP  [R805H24]  24.69 84.17 0 top
EL4303  0R5J-5-GP  [R805H24]  17.19 81.65 270 top
EL4304  0R5J-5-GP  [R805H24]  17.19 79.85 270 top
EU3601  ESD3V3U4ULC-GP  [LGA9G2310H13]  19.41 53.31 270 top
EU3602  AZC099-04S-1-GP  [SOT-6H58]  20.32 53.23 270 bottom
EU3603  ESD3V3U4ULC-GP  [LGA9G2310H13]  19.61 31.08 270 top
EU3604  AZC099-04S-1-GP  [SOT-6H58]  19.89 33.16 90 bottom
EU3801  ESD3V3U4ULC-GP  [LGA9G2310H13]  14.04 91.28 270 top
EU3802  ESD3V3U4ULC-GP  [LGA9G2310H13]  14.02 98.52 270 top
EU3803  ESD3V3U4ULC-GP  [LGA9G2310H13]  14.02 95.09 90 top
EU3804  AZ5315-02F-GP  [SOT883-1D0-321H20]  16.08 93.06 270 top
F5501  POLYSW-1D1A24V-GP-U  [POLYSW-4633-UH43]  68.65 96.99 0 top
F5502  POLYSW-D5A6V-1-GP  [POLYSW-2114H50]  55.88 99.2 180 top
F5503  POLYSW-1D1A24V-GP-U  [POLYSW-4633-UH43]  74.83 97.22 180 top
F5504  POLYSW-1D1A6V-9-GP-U  [POLYSW-2114H30]  56.79 96.21 270 top
F5701  POLYSW-1D1A6V-9-GP-U  [POLYSW-2114H30]  21.94 58.46 270 top
F6501  POLYSW-D5A6V-1-GP  [POLYSW-2114H50]  141.65 20.77 90 bottom
FAN1  ACES-CON4-29-GP  [50224-0040N-001]  159.96 75.71 270 bottom
G1801  GAP-OPEN  [CON2O-U]  67.74 5.53 90 bottom
GMR1  HGDEDM013A-GP  [OPLGA4-0913H22]  7.26 85.48 180 top
GPU1  UNI-CONN48-6R-GP-U1  [XBGCB5009]  174.7 89.86 270 bottom
GPU2  UNI-CONN28-6R-GP-U  [XBGCB5008]  174.7 75.98 90 bottom
H2  HOLE335R178-GP  [HOLE335R178]  175.7 101.21 180 bottom
H3  HOLE335R229-GP  [HOLE335R229]  162 39.06 180 bottom
H4  HOLE335R178-GP  [HOLE335R178]  188.47 21.41 180 bottom
H5  HOLE335R229-GP  [HOLE335R229]  115.9 3.99 180 bottom
H6  HOLE335R229-GP  [HOLE335R229]  25.9 3.99 180 bottom
H7  HOLE335R178-GP  [HOLE335R178]  128.85 84.21 180 bottom
H8  HOLE335R178-GP  [HOLE335R178]  102.85 84.21 180 bottom
H9  HOLE335R178-GP  [HOLE335R178]  128.85 29.21 180 bottom
H10  HOLE335R178-GP  [HOLE335R178]  102.85 29.21 180 bottom
HDA27  ALC3253-CG-GP  [QFN48J6-G465H40]  23.24 17.11 270 top
HDD1  FOX-CON20-1-GP-U1  [GS12201-1011-9H]  180.52 19.83 90 bottom
HDMI1  SKT-HDMI23-91-GP-U  [SKT-HDMI23-188137-2]  4.6 74.58 90 bottom
HPMIC1  AUDIO-JK522-GP  [AJ3R2D-Y050-412]  4.2 17.09 90 bottom
HS1  STF217R115H101-GP  [STF217R115H101]  10.8 86.51 180 bottom
